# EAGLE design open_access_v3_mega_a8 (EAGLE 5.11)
DIGIKEY: 709-1189-1-ND

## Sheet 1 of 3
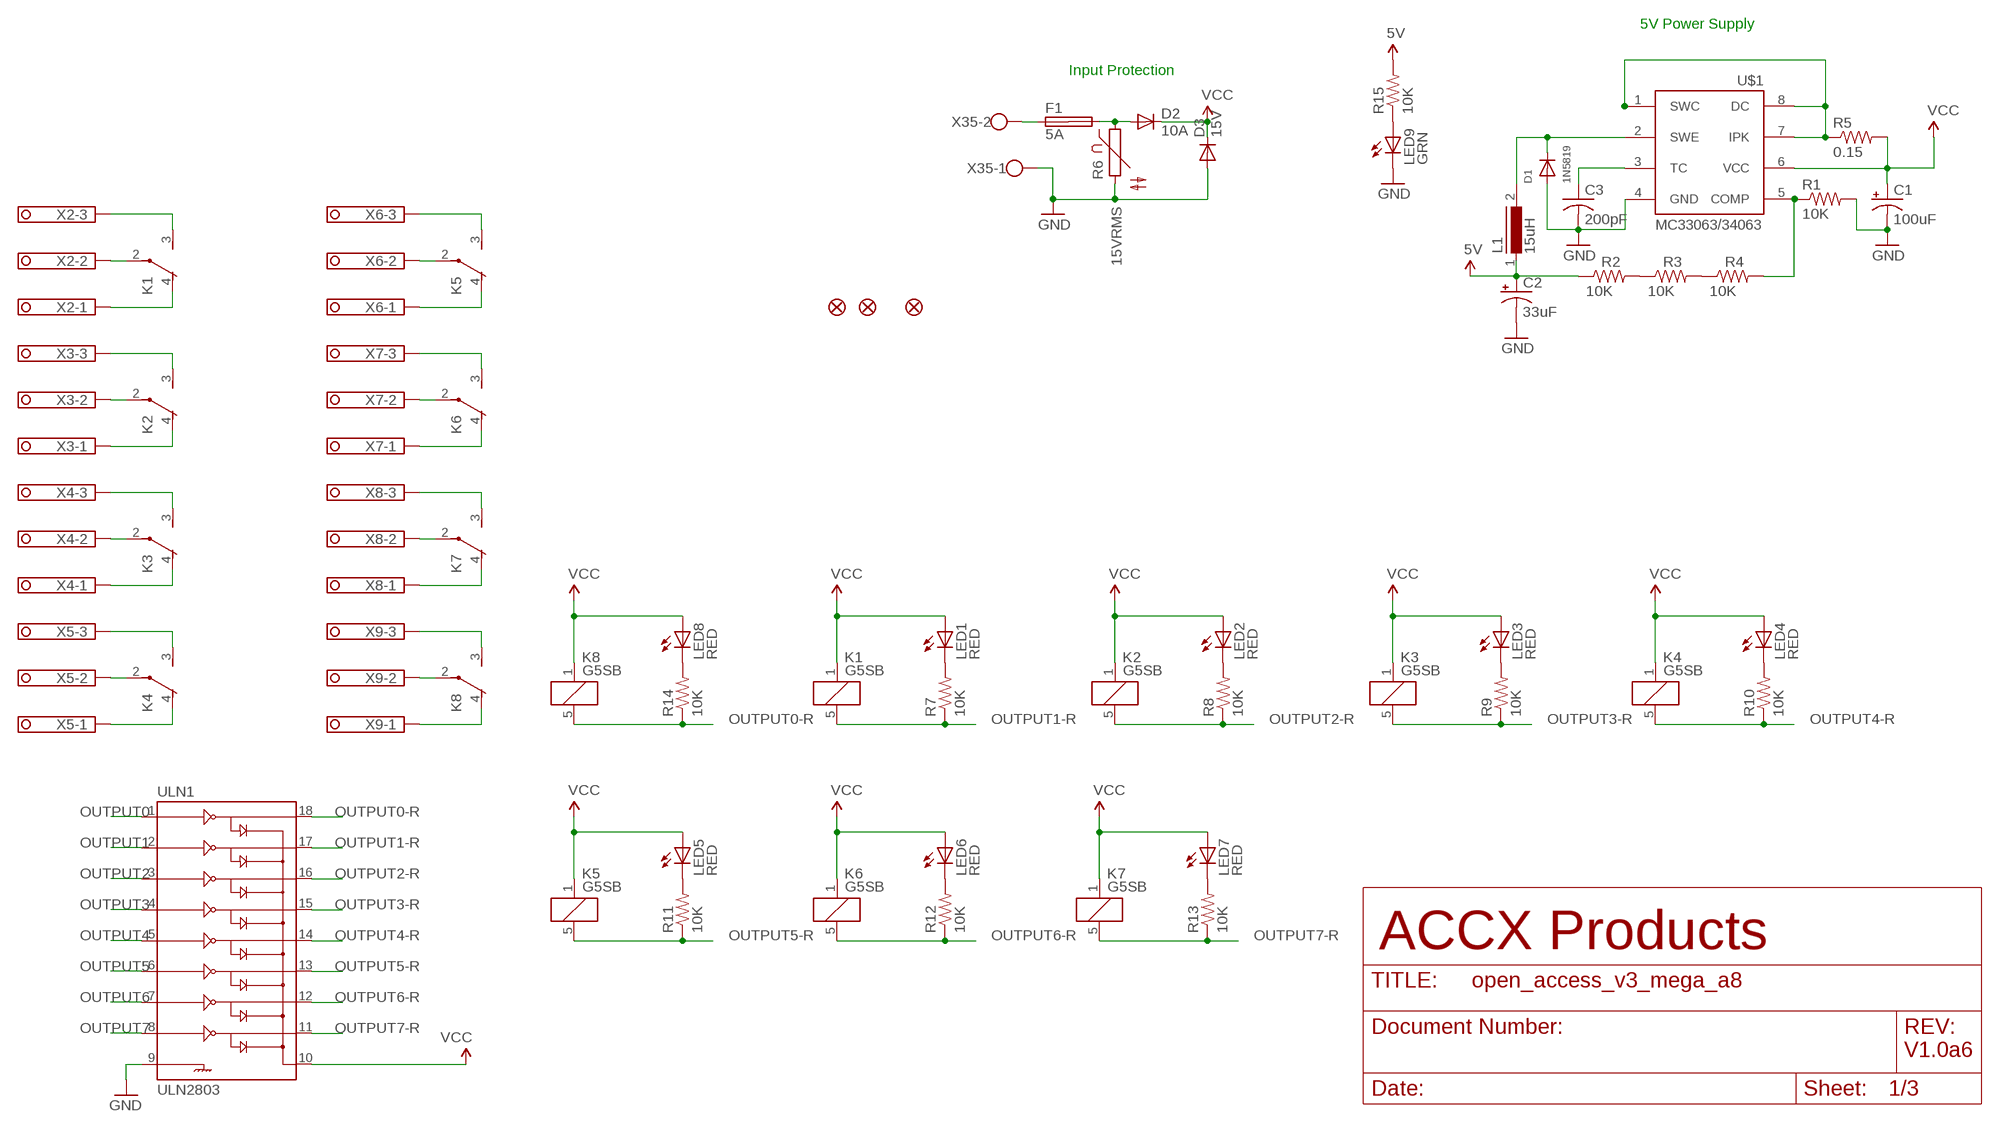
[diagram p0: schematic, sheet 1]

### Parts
C1  100uF  CPOL-US140CLH-0810  [140CLH-0810]
C2  33uF  CPOL-US153CLV-0605  [153CLV-0605]
C3  200pF  C-USC0805  [C0805]
D1  1N5819  DIODESOD-123  [SOD-123]
D2  10A  DIODE-SMC  [SMC]
D3  15V  DIODE-SOD123  [SOD123]
F1  5A  5X20MMCLIP  [SHK20Q]
JP3  FIDUCIAL1.5X3  [FIDUCIAL-1.5X3]
JP4  FIDUCIAL1.5X3  [FIDUCIAL-1.5X3]
JP5  FIDUCIAL1.5X3  [FIDUCIAL-1.5X3]
K1  G5SB  [G5SB]
K2  G5SB  [G5SB]
K3  G5SB  [G5SB]
K4  G5SB  [G5SB]
K5  G5SB  [G5SB]
K6  G5SB  [G5SB]
K7  G5SB  [G5SB]
K8  G5SB  [G5SB]
L1  15uH  SLF7045  [SLF7045]
LED1  RED  LEDCHIP-LED0805  [CHIP-LED0805]
LED2  RED  LEDCHIP-LED0805  [CHIP-LED0805]
LED3  RED  LEDCHIP-LED0805  [CHIP-LED0805]
LED4  RED  LEDCHIP-LED0805  [CHIP-LED0805]
LED5  RED  LEDCHIP-LED0805  [CHIP-LED0805]
LED6  RED  LEDCHIP-LED0805  [CHIP-LED0805]
LED7  RED  LEDCHIP-LED0805  [CHIP-LED0805]
LED8  RED  LEDCHIP-LED0805  [CHIP-LED0805]
LED9  GRN  LEDCHIP-LED0805  [CHIP-LED0805]
R1  10K  R-US_R0805  [R0805]
R2  10K  R-US_R0805  [R0805]
R3  10K  R-US_R0805  [R0805]
R4  10K  R-US_R0805  [R0805]
R5  0.15  R-US_R0805  [R0805]
R6  15VRMS  S10K40  [S10K40]
R7  10K  R-US_R0805  [R0805]
R8  10K  R-US_R0805  [R0805]
R9  10K  R-US_R0805  [R0805]
R10  10K  R-US_R0805  [R0805]
R11  10K  R-US_R0805  [R0805]
R12  10K  R-US_R0805  [R0805]
R13  10K  R-US_R0805  [R0805]
R14  10K  R-US_R0805  [R0805]
R15  10K  R-US_R0805  [R0805]
U$1  MC33063/MC34063D  [SO08]
ULN1  ULN2803  ULN2803SOICW  [SO18L]
X2  1751251  [1751251]
X3  1751251  [1751251]
X4  1751251  [1751251]
X5  1751251  [1751251]
X6  1751251  [1751251]
X7  1751251  [1751251]
X8  1751251  [1751251]
X9  1751251  [1751251]
X35  W237-102  [W237-102]

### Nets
5V [1A_power]: C2.+ L1.1 R2.1 R15.2 ; also sheet 2,3
GND: C1.- C2.- C3.2 D1.A D3.A LED9.C R1.2 R6.2 U$1.4(GND) ULN1.9 X35.1 ; also sheet 2,3
N$1 [1A_power]: R2.2 R3.1
N$2 [1A_power]: R3.2 R4.1
N$3 [1A_power]: R5.1 U$1.1(SWC) U$1.7(IPK) U$1.8(DC)
N$4: F1.1A X35.2
N$5: R1.1 R4.2 U$1.5(COMP)
N$6: C3.1 U$1.3(TC)
N$8 [1A_power]: D2.A F1.2A R6.1
N$9: LED2.C R8.2
N$10 [5A_power]: K1.2(U:P) X2.2
N$11 [5A_power]: K1.3(U:S) X2.3
N$12 [5A_power]: K1.4(U:O) X2.1
N$13 [5A_power]: K2.2(U:P) X3.2
N$14 [5A_power]: K2.3(U:S) X3.3
N$15 [5A_power]: K2.4(U:O) X3.1
N$16 [5A_power]: K3.2(U:P) X4.2
N$17 [5A_power]: K3.3(U:S) X4.3
N$18 [5A_power]: K3.4(U:O) X4.1
N$19 [5A_power]: K4.2(U:P) X5.2
N$20 [5A_power]: K4.3(U:S) X5.3
N$21 [5A_power]: K4.4(U:O) X5.1
N$22 [5A_power]: K5.2(U:P) X6.2
N$23 [5A_power]: K5.3(U:S) X6.3
N$24 [5A_power]: K5.4(U:O) X6.1
N$25 [5A_power]: K6.2(U:P) X7.2
N$26 [5A_power]: K6.3(U:S) X7.3
N$27 [5A_power]: K6.4(U:O) X7.1
N$28 [5A_power]: K7.2(U:P) X8.2
N$29 [5A_power]: K7.3(U:S) X8.3
N$30 [5A_power]: K7.4(U:O) X8.1
N$31 [5A_power]: K8.2(U:P) X9.2
N$32 [5A_power]: K8.3(U:S) X9.3
N$34: LED3.C R9.2
N$35: LED1.C R7.2
N$36: LED4.C R10.2
N$37: LED5.C R11.2
N$38: LED6.C R12.2
N$39: LED7.C R13.2
N$40: LED8.C R14.2
N$41: LED9.A R15.1
N$81: D1.C L1.2 U$1.2(SWE)
N$255 [5A_power]: K8.4(U:O) X9.1
OUTPUT0: ULN1.1 ; also sheet 3
OUTPUT0-R: K8.5 R14.1 ULN1.18
OUTPUT1: ULN1.2 ; also sheet 3
OUTPUT1-R: K1.5 R7.1 ULN1.17
OUTPUT2: ULN1.3 ; also sheet 3
OUTPUT2-R: K2.5 R8.1 ULN1.16
OUTPUT3: ULN1.4 ; also sheet 3
OUTPUT3-R: K3.5 R9.1 ULN1.15
OUTPUT4: ULN1.5 ; also sheet 3
OUTPUT4-R: K4.5 R10.1 ULN1.14
OUTPUT5: ULN1.6 ; also sheet 3
OUTPUT5-R: K5.5 R11.1 ULN1.13
OUTPUT6: ULN1.7 ; also sheet 3
OUTPUT6-R: K6.5 R12.1 ULN1.12
OUTPUT7: ULN1.8 ; also sheet 3
OUTPUT7-R: K7.5 R13.1 ULN1.11
VCC [1A_power]: C1.+ D2.C D3.C K1.1 K2.1 K3.1 K4.1 K5.1 K6.1 K7.1 K8.1 LED1.A LED2.A LED3.A LED4.A LED5.A LED6.A LED7.A LED8.A R5.2 U$1.6(VCC) ULN1.10 ; also sheet 2
Unconnected: F1.1B F1.2B

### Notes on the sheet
- 5V Power Supply
- Input Protection
- ACCX Products
- V1.0a6

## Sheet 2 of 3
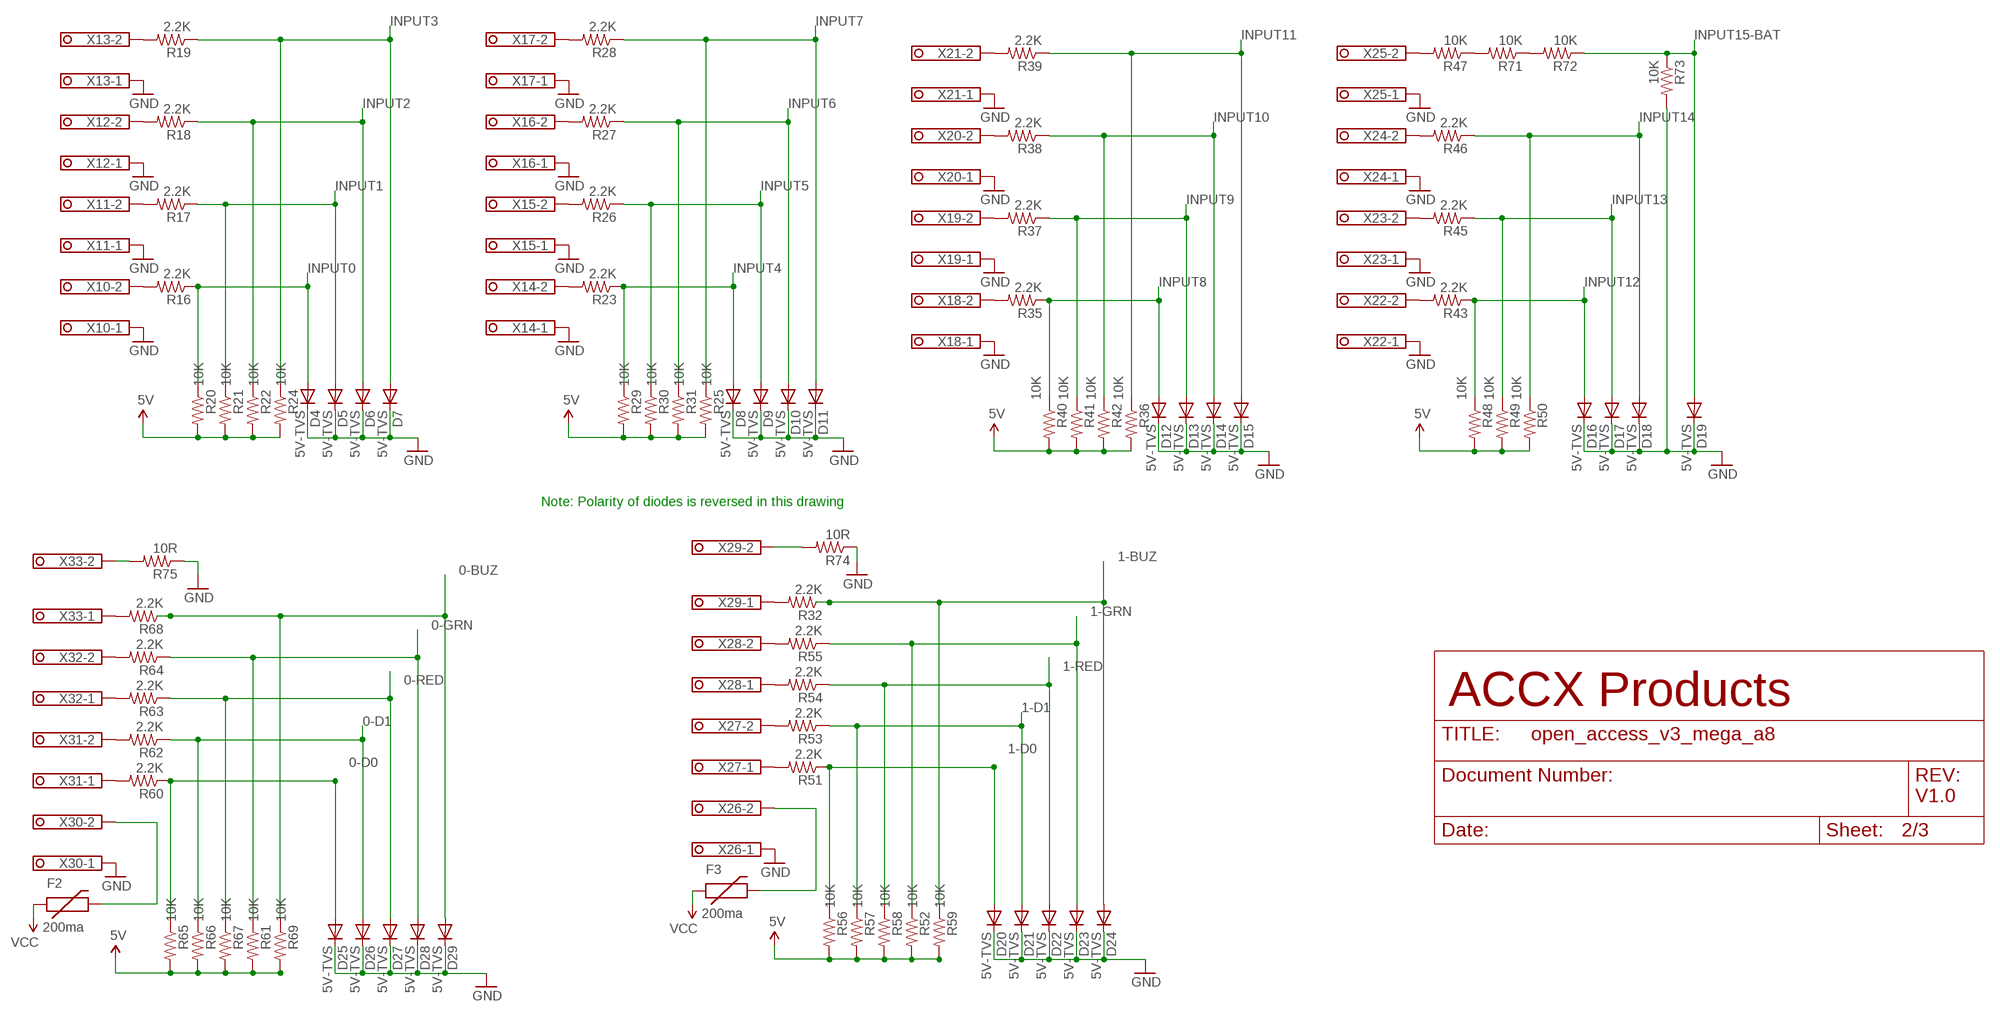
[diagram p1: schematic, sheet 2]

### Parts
D4  5V-TVS  DIODE-SOD123  [SOD123]
D5  5V-TVS  DIODE-SOD123  [SOD123]
D6  5V-TVS  DIODE-SOD123  [SOD123]
D7  5V-TVS  DIODE-SOD123  [SOD123]
D8  5V-TVS  DIODE-CREV  [SOT123-CREV]
D9  5V-TVS  DIODE-CREV  [SOT123-CREV]
D10  5V-TVS  DIODE-CREV  [SOT123-CREV]
D11  5V-TVS  DIODE-CREV  [SOT123-CREV]
D12  5V-TVS  DIODE-SOD123  [SOD123]
D13  5V-TVS  DIODE-SOD123  [SOD123]
D14  5V-TVS  DIODE-SOD123  [SOD123]
D15  5V-TVS  DIODE-SOD123  [SOD123]
D16  5V-TVS  DIODE-SOD123  [SOD123]
D17  5V-TVS  DIODE-SOD123  [SOD123]
D18  5V-TVS  DIODE-SOD123  [SOD123]
D19  5V-TVS  DIODE-SOD123  [SOD123]
D20  5V-TVS  DIODE-SOD123  [SOD123]
D21  5V-TVS  DIODE-SOD123  [SOD123]
D22  5V-TVS  DIODE-SOD123  [SOD123]
D23  5V-TVS  DIODE-SOD123  [SOD123]
D24  5V-TVS  DIODE-SOD123  [SOD123]
D25  5V-TVS  DIODE-SOD123  [SOD123]
D26  5V-TVS  DIODE-SOD123  [SOD123]
D27  5V-TVS  DIODE-SOD123  [SOD123]
D28  5V-TVS  DIODE-SOD123  [SOD123]
D29  5V-TVS  DIODE-SOD123  [SOD123]
F2  200ma  PTCSMD  [PTC-1206]
F3  200ma  PTCSMD  [PTC-1206]
R16  2.2K  R-US_R0805  [R0805]
R17  2.2K  R-US_R0805  [R0805]
R18  2.2K  R-US_R0805  [R0805]
R19  2.2K  R-US_R0805  [R0805]
R20  10K  R-US_R0805  [R0805]
R21  10K  R-US_R0805  [R0805]
R22  10K  R-US_R0805  [R0805]
R23  2.2K  R-US_R0805  [R0805]
R24  10K  R-US_R0805  [R0805]
R25  10K  R-US_R0805  [R0805]
R26  2.2K  R-US_R0805  [R0805]
R27  2.2K  R-US_R0805  [R0805]
R28  2.2K  R-US_R0805  [R0805]
R29  10K  R-US_R0805  [R0805]
R30  10K  R-US_R0805  [R0805]
R31  10K  R-US_R0805  [R0805]
R32  2.2K  R-US_R0805  [R0805]
R35  2.2K  R-US_R0805  [R0805]
R36  10K  R-US_R0805  [R0805]
R37  2.2K  R-US_R0805  [R0805]
R38  2.2K  R-US_R0805  [R0805]
R39  2.2K  R-US_R0805  [R0805]
R40  10K  R-US_R0805  [R0805]
R41  10K  R-US_R0805  [R0805]
R42  10K  R-US_R0805  [R0805]
R43  2.2K  R-US_R0805  [R0805]
R45  2.2K  R-US_R0805  [R0805]
R46  2.2K  R-US_R0805  [R0805]
R47  10K  R-US_R0805  [R0805]
R48  10K  R-US_R0805  [R0805]
R49  10K  R-US_R0805  [R0805]
R50  10K  R-US_R0805  [R0805]
R51  2.2K  R-US_R0805  [R0805]
R52  10K  R-US_R0805  [R0805]
R53  2.2K  R-US_R0805  [R0805]
R54  2.2K  R-US_R0805  [R0805]
R55  2.2K  R-US_R0805  [R0805]
R56  10K  R-US_R0805  [R0805]
R57  10K  R-US_R0805  [R0805]
R58  10K  R-US_R0805  [R0805]
R59  10K  R-US_R0805  [R0805]
R60  2.2K  R-US_R0805  [R0805]
R61  10K  R-US_R0805  [R0805]
R62  2.2K  R-US_R0805  [R0805]
R63  2.2K  R-US_R0805  [R0805]
R64  2.2K  R-US_R0805  [R0805]
R65  10K  R-US_R0805  [R0805]
R66  10K  R-US_R0805  [R0805]
R67  10K  R-US_R0805  [R0805]
R68  2.2K  R-US_R0805  [R0805]
R69  10K  R-US_R0805  [R0805]
R71  10K  R-US_R0805  [R0805]
R72  10K  R-US_R0805  [R0805]
R73  10K  R-US_R0805  [R0805]
R74  10R  R-US_R0805  [R0805]
R75  10R  R-US_R0805  [R0805]
X10  1751248  [1751248]
X11  1751248  [1751248]
X12  1751248  [1751248]
X13  1751248  [1751248]
X14  1751248  [1751248]
X15  1751248  [1751248]
X16  1751248  [1751248]
X17  1751248  [1751248]
X18  1751248  [1751248]
X19  1751248  [1751248]
X20  1751248  [1751248]
X21  1751248  [1751248]
X22  1751248  [1751248]
X23  1751248  [1751248]
X24  1751248  [1751248]
X25  1751248  [1751248]
X26  1751248  [1751248]
X27  1751248  [1751248]
X28  1751248  [1751248]
X29  1751248  [1751248]
X30  1751248  [1751248]
X31  1751248  [1751248]
X32  1751248  [1751248]
X33  1751248  [1751248]

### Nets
0-BUZ: D29.A R68.1 R69.1 ; also sheet 3
0-D0: D25.A R60.1 R65.1 ; also sheet 3
0-D1: D26.A R62.1 R66.1 ; also sheet 3
0-GRN: D28.A R61.1 R64.1 ; also sheet 3
0-RED: D27.A R63.1 R67.1 ; also sheet 3
1-BUZ: D24.A R32.1 R59.1 ; also sheet 3
1-D0: D20.A R51.1 R56.1 ; also sheet 3
1-D1: D21.A R53.1 R57.1 ; also sheet 3
1-GRN: D23.A R52.1 R55.1 ; also sheet 3
1-RED: D22.A R54.1 R58.1 ; also sheet 3
5V [1A_power]: R20.2 R21.2 R22.2 R24.2 R25.2 R29.2 R30.2 R31.2 R36.2 R40.2 R41.2 R42.2 R48.2 R49.2 R50.2 R52.2 R56.2 R57.2 R58.2 R59.2 R61.2 R65.2 R66.2 R67.2 R69.2 ; also sheet 1,3
GND: D4.C D5.C D6.C D7.C D8.C D9.C D10.C D11.C D12.C D13.C D14.C D15.C D16.C D17.C D18.C D19.C D20.C D21.C D22.C D23.C D24.C D25.C D26.C D27.C D28.C D29.C R73.2 R74.1 R75.1 X10.1 X11.1 X12.1 X13.1 X14.1 X15.1 X16.1 X17.1 X18.1 X19.1 X20.1 X21.1 X22.1 X23.1 X24.1 X25.1 X26.1 X30.1 ; also sheet 1,3
INPUT0: D4.A R16.1 R20.1 ; also sheet 3
INPUT1: D5.A R17.1 R21.1 ; also sheet 3
INPUT2: D6.A R18.1 R22.1 ; also sheet 3
INPUT3: D7.A R19.1 R24.1 ; also sheet 3
INPUT4: D8.A R23.1 R29.1 ; also sheet 3
INPUT5: D9.A R26.1 R30.1 ; also sheet 3
INPUT6: D10.A R27.1 R31.1 ; also sheet 3
INPUT7: D11.A R25.1 R28.1 ; also sheet 3
INPUT8: D12.A R35.1 R40.1 ; also sheet 3
INPUT9: D13.A R37.1 R41.1 ; also sheet 3
INPUT10: D14.A R38.1 R42.1 ; also sheet 3
INPUT11: D15.A R36.1 R39.1 ; also sheet 3
INPUT12: D16.A R43.1 R48.1 ; also sheet 3
INPUT13: D17.A R45.1 R49.1 ; also sheet 3
INPUT14: D18.A R46.1 R50.1 ; also sheet 3
INPUT15-BAT: D19.A R72.1 R73.1 ; also sheet 3
N$46 [1A_power]: F2.2 X30.2
N$47: F3.2 X26.2
N$50: R16.2 X10.2
N$51: R17.2 X11.2
N$52: R18.2 X12.2
N$53: R19.2 X13.2
N$54: R23.2 X14.2
N$55: R26.2 X15.2
N$56: R27.2 X16.2
N$57: R28.2 X17.2
N$61: R35.2 X18.2
N$62: R37.2 X19.2
N$63: R38.2 X20.2
N$64: R39.2 X21.2
N$65: R43.2 X22.2
N$66: R45.2 X23.2
N$67: R46.2 X24.2
N$68: R47.2 X25.2
N$69: R51.2 X27.1
N$70: R53.2 X27.2
N$71: R54.2 X28.1
N$72: R55.2 X28.2
N$73: R32.2 X29.1
N$74: R62.2 X31.2
N$75: R60.2 X31.1
N$76: R63.2 X32.1
N$77: R64.2 X32.2
N$78: R68.2 X33.1
N$82: R47.1 R71.2
N$83: R71.1 R72.2
N$84: R74.2 X29.2
N$85: R75.2 X33.2
VCC [1A_power]: F2.1 F3.1 ; also sheet 1

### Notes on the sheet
- Note: Polarity of diodes is reversed in this drawing
- ACCX Products
- V1.0

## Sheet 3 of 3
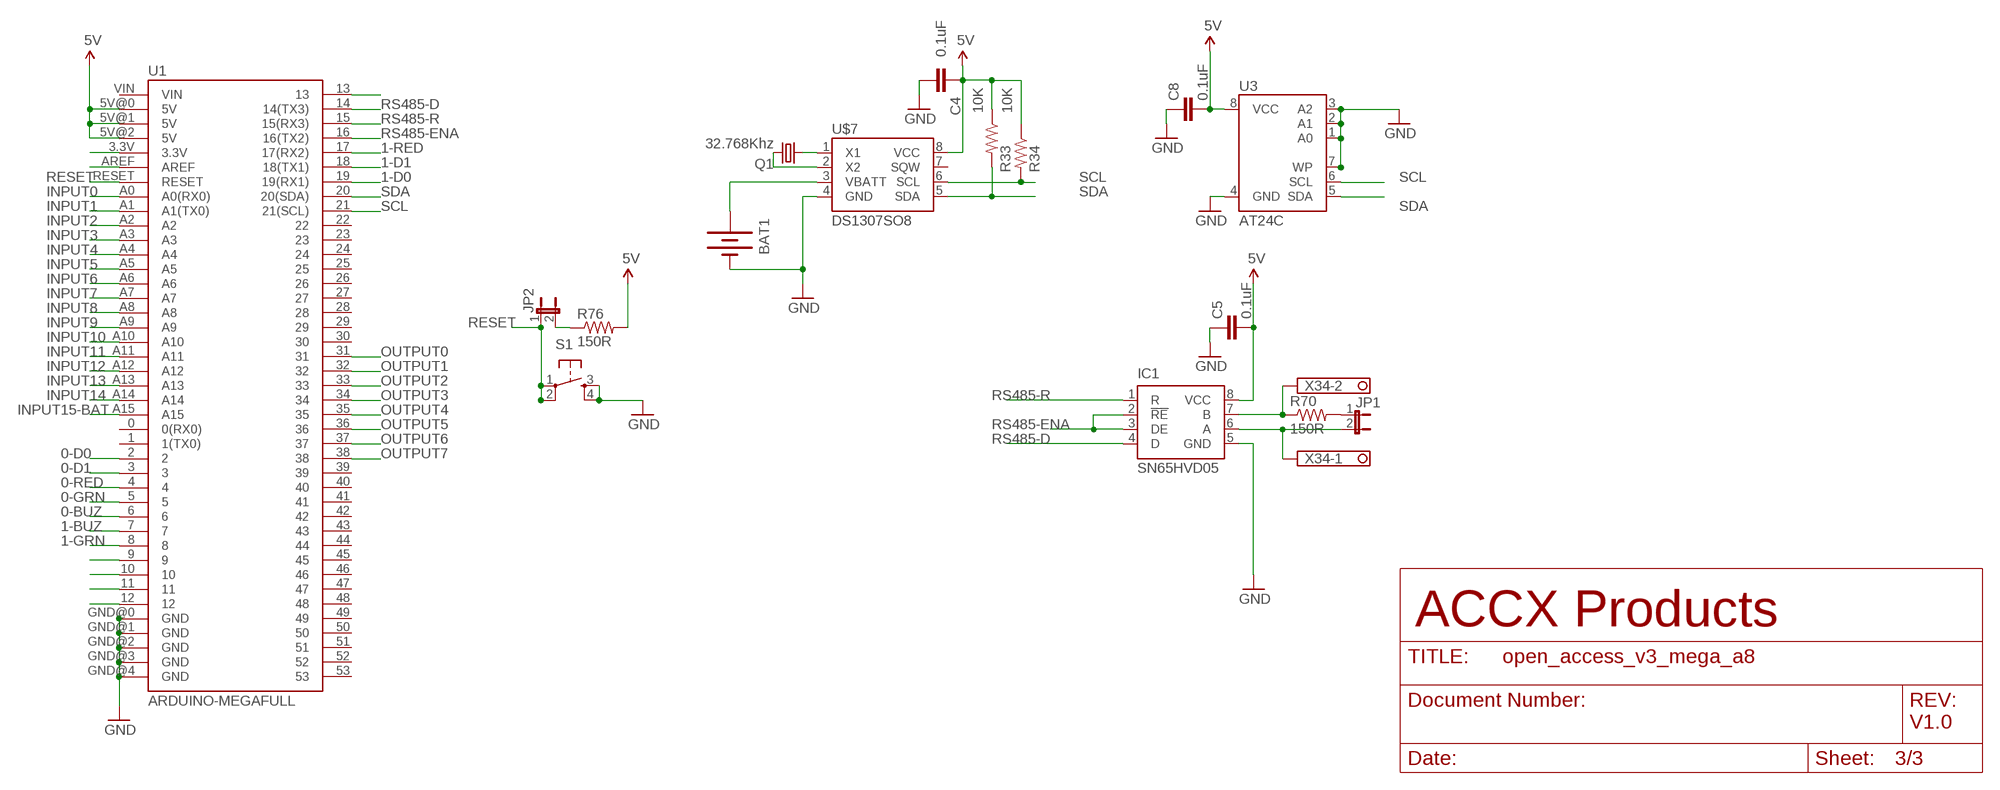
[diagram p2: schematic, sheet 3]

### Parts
BAT1  BATTERY20PTH  [BATTCOM_20MM_PTH]
C4  0.1uF  CAP0805  [0805]
C5  0.1uF  CAP0805  [0805]
C8  0.1uF  CAP0805  [0805]
IC1  SN65HVD05  SN65176D  [SO-08]
JP1  JP1E  [JP1]
JP2  JP1E  [JP1]
Q1  32.768Khz  CRYSTALMM20SS  [MM20SS]
R33  10K  R-US_R0805  [R0805]
R34  10K  R-US_R0805  [R0805]
R70  150R  R-US_R0805  [R0805]
R76  150R  R-US_R0805  [R0805]
S1  TAC_SWITCHSMD  [TACTILE_SWITCH_SMD]
U1  ARDUINO-MEGAFULL  [ARDUINO_MEGA]
U3  AT24C  [SOIC8]
U$7  DS1307SO8  [SO08]
X34  1751248  [1751248]

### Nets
0-BUZ: U1.6 ; also sheet 2
0-D0: U1.2 ; also sheet 2
0-D1: U1.3 ; also sheet 2
0-GRN: U1.5 ; also sheet 2
0-RED: U1.4 ; also sheet 2
1-BUZ: U1.7 ; also sheet 2
1-D0: U1.19(19(RX1)) ; also sheet 2
1-D1: U1.18(18(TX1)) ; also sheet 2
1-GRN: U1.8 ; also sheet 2
1-RED: U1.17(17(RX2)) ; also sheet 2
5V [1A_power]: C4.2 C5.2 C8.2 IC1.8(VCC) R33.1 R34.1 R76.2 U1.5V@0(5V) U1.5V@1(5V) U1.5V@2(5V) U3.8(VCC) U$7.8(VCC) ; also sheet 1,2
GND: BAT1.2(-) C4.1 C5.1 C8.1 IC1.5(GND) S1.3 S1.4 U1.GND@0(GND) U1.GND@1(GND) U1.GND@2(GND) U1.GND@3(GND) U1.GND@4(GND) U3.1(A0) U3.2(A1) U3.3(A2) U3.4(GND) U3.7(WP) U$7.4(GND) ; also sheet 1,2
INPUT0: U1.A0(A0(RX0)) ; also sheet 2
INPUT1: U1.A1(A1(TX0)) ; also sheet 2
INPUT2: U1.A2 ; also sheet 2
INPUT3: U1.A3 ; also sheet 2
INPUT4: U1.A4 ; also sheet 2
INPUT5: U1.A5 ; also sheet 2
INPUT6: U1.A6 ; also sheet 2
INPUT7: U1.A7 ; also sheet 2
INPUT8: U1.A8 ; also sheet 2
INPUT9: U1.A9 ; also sheet 2
INPUT10: U1.A10 ; also sheet 2
INPUT11: U1.A11 ; also sheet 2
INPUT12: U1.A12 ; also sheet 2
INPUT13: U1.A13 ; also sheet 2
INPUT14: U1.A14 ; also sheet 2
INPUT15-BAT: U1.A15 ; also sheet 2
N$42: U1.12
N$43: U1.11
N$44: U1.10
N$45: U1.9
N$49: IC1.6(A) JP1.2 X34.1
N$58: Q1.1 U$7.1(X1)
N$59: Q1.4 U$7.2(X2)
N$60: BAT1.1(+) U$7.3(VBATT)
N$79: JP2.2 R76.1
N$86: JP1.1 R70.2
N$91: U1.3.3V
N$92: U1.AREF
N$93: U1.13
OUTPUT0: U1.31 ; also sheet 1
OUTPUT1: U1.32 ; also sheet 1
OUTPUT2: U1.33 ; also sheet 1
OUTPUT3: U1.34 ; also sheet 1
OUTPUT4: U1.35 ; also sheet 1
OUTPUT5: U1.36 ; also sheet 1
OUTPUT6: U1.37 ; also sheet 1
OUTPUT7: U1.38 ; also sheet 1
RESET: JP2.1 S1.1 S1.2 U1.RESET
RS485-B: IC1.7(B) R70.1 X34.2
RS485-D: IC1.4(D) U1.14(14(TX3))
RS485-ENA: IC1.2(!RE) IC1.3(DE) U1.16(16(TX2))
RS485-R: IC1.1(R) U1.15(15(RX3))
SCL: R34.2 U1.21(21(SCL)) U3.6(SCL) U$7.6(SCL)
SDA: R33.2 U1.20(20(SDA)) U3.5(SDA) U$7.5(SDA)
Unconnected: U1.0(0(RX0)) U1.1(1(TX0)) U1.22 U1.23 U1.24 U1.25 U1.26 U1.27 U1.28 U1.29 U1.30 U1.39 U1.40 U1.41 U1.42 U1.43 U1.44 U1.45 U1.46 U1.47 U1.48 U1.49 U1.50 U1.51 U1.52 U1.53 U1.VIN U$7.7(SQW)

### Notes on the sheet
- ACCX Products
- V1.0

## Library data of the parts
BAT1 = SparkFun:BATTERY: Battery Holders
C1 C2 = resistor:CPOL-US: POLARIZED CAPACITOR, American symbol
C3 = resistor:C-US: CAPACITOR, American symbol
C4 C5 C8 = SparkFun:CAP: Capacitor
D1 = adafruit:DIODE: Diode
D2-D7 D12-D29 = diode:DIODE-: DIODE
D8-D11 = 23B_Shop_Library:DIODE-CREV
F1 = 23B_Shop_Library:5X20MMCLIP: FUSE HOLDER Littelfuse 01110506H 5x20mm clips. Mouser part #576-01110506H
F2 F3 = SparkFun:PTC: Resettable Fuse PTC
IC1 = texas:SN65176: DIFFERENTIAL BUS TRANSCEIVER Source: http://focus.ti.com .. sn65176b.pdf; MF: TEXAS INSTRUMENTS; MPN: SN65176BD; OC_FARNELL: 9589970; OC_NEWARK: 08F5891
JP1 JP2 = jumper:JP1E: JUMPER
JP3-JP5 = SparkFun:FIDUCIAL: Fiducial Alignment Points
K1-K8 = relay:G5SB: Compact Single-pole Relay for Switching 5 A Source: http://www.omron.com/ecb/products/pry/121/g5sb.html; OC_FARNELL: unknown; OC_NEWARK: unknown
L1 = inductors:SLF7045: SMD Inductors(Coils) For Power Line (Wound, Magnetic Shielded)
LED1-LED9 = adafruit:LED: LED
Q1 = crystal:CRYSTAL: CRYSTAL; OC_FARNELL: unknown; OC_NEWARK: unknown
R1-R5 R7-R43 R45-R76 = resistor:R-US_: RESISTOR, American symbol
R6 = varistor:S10K40: VARISTOR
S1 = SparkFun:TAC_SWITCH: Momentary Switch Button commonly used for reset or general input. Spark Fun Electronics SKU : COM-00097
U1 = SparkFun:ARDUINO-MEGA: Arduino Mega footprint connections
U3 = atmel:AT24C*: 2-wire serial EEPROM
U$1 = adafruit:MC33063/MC34063: MC33063 and MC34063 Basic DC/DC converter with internal power-NPN transistor, 100KHz, 1.5A peak switch current. 3-40 input/output.
U$7 = SparkFun:DS1307
ULN1 = SparkFun:ULN2803: Darlington Driver ULN2803 Darlington array. 500mA max per channel, 8-channel package. Spark Fun Electronics SKU : COM-00312
X2-X9 = con-phoenix-350:1751251: MKDS 1/ 3-3,5 Printklemme Nennstrom: 10 A Bemessungsspannung: 160 V Raster: 3,5 mm Polzahl: 3 Montageart: Löten Anschlussart: Schraubanschluss Anschlussrichtung vom Leiter zur Platine: 0° Source: http://eshop.phoenixcontact.com .. 1751251.pdf; OC_FARNELL: unknown; OC_NEWARK: unknown
X10-X34 = con-phoenix-350:1751248: MKDS 1/ 2-3,5 Printklemme; OC_FARNELL: unknown; OC_NEWARK: unknown
X35 = 23B_Shop_Library:W237-102: WAGO SCREW CLAMP

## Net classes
0 signals: width 0.254 mm, clearance 0.254 mm
1 power signals: width 0.305 mm, clearance 0.305 mm
2 1A_power: width 0.406 mm, clearance 0.305 mm
3 5A_power: width 2.54 mm, clearance 0.61 mm

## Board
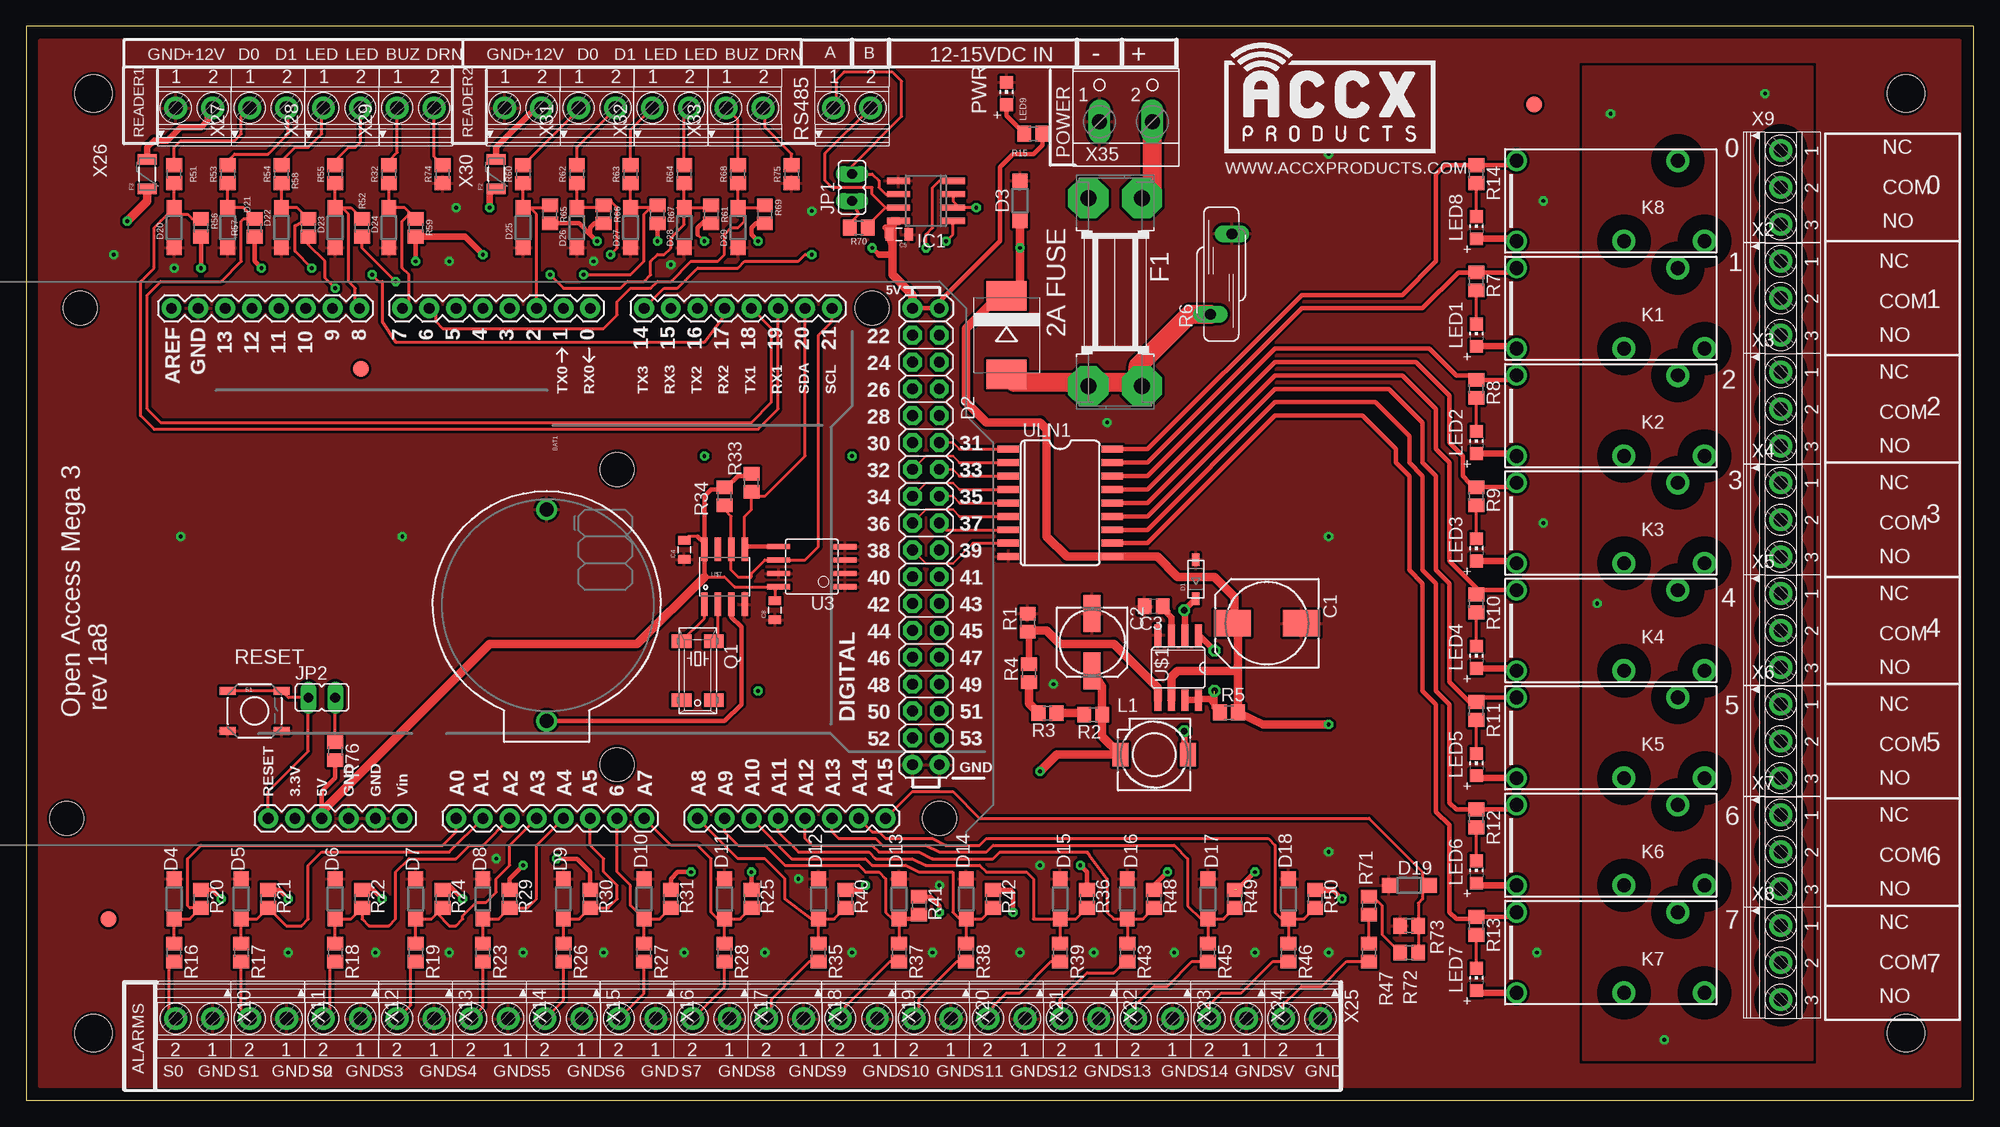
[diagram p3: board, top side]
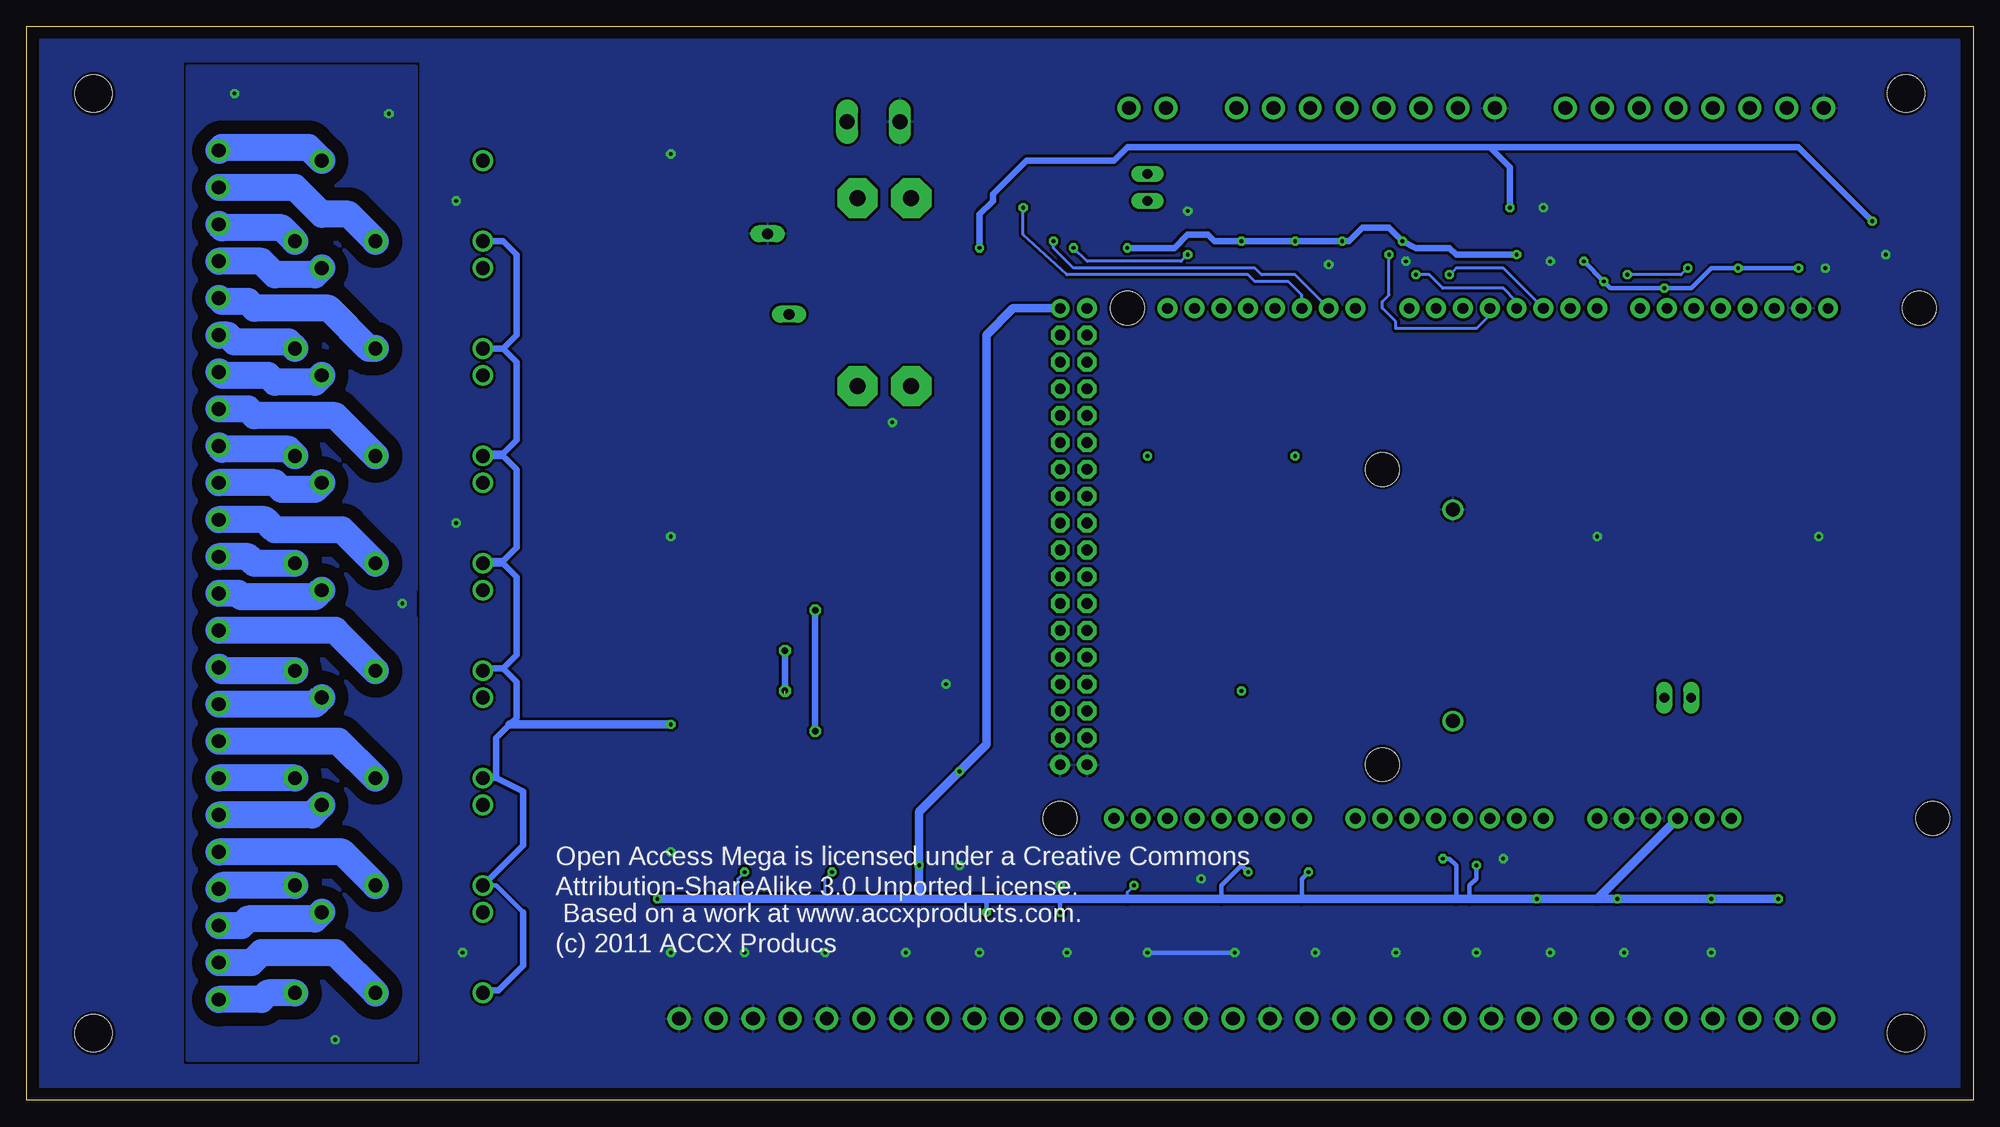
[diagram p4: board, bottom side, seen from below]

Size 184.15 x 101.6 mm. Coordinates in mm from the lower left corner, seen from the top.
Outline: 0,0 184.15,0 184.15,101.6 0,101.6 0,0
Copper layers (1*16): Top 0.035mm / dielectric 1.5mm / Bottom 0.035mm
Design rules "SparkFun": minimum track width 8mil, minimum drill 20mil, track to track 8mil, track to pad 8mil, pad to pad 8mil, via to via 8mil, smd to smd 8mil, copper to edge 10mil, drill to drill 8mil, minimum pad ring 12mil, minimum via ring 10mil, stop-mask expansion 4mil, vias tented up to drill 25mil, thermal gap 10mil
Holes 3.56 mm at 6.35,6.35 6.35,95.25 177.8,6.35 177.8,95.25

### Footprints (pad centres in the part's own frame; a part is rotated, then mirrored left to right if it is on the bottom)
BATTCOM_20MM_PTH = drill 1.3 round: 1 20,0; 2 0,0
140CLH-0810 = smd 3.5 x 2.5: + 3.25,0; - -3.25,0
153CLV-0605 = smd 3.5 x 1.6: + 2.7,0; - -2.7,0
C0805 = smd 1.3 x 1.5: 1 -0.85,0; 2 0.85,0
0805 = smd 0.8 x 1.2: 1 -0.9,0; 2 0.9,0
SOD-123 = smd 1.2 x 0.7: A 1.85,0; C -1.85,0
SMC = smd 2.8 x 3.8: A 3.7,0; C -3.7,0
SOD123 = smd 1.4 x 1.4: A 1.9,0; C -1.9,0
SOT123-CREV = smd 1.4 x 1.4: A 1.9,0; C -1.9,0
SHK20Q = drill 1.5 pad 3.81 octagon: 1A -8.89,2.54; 1B -8.89,-2.54; 2A 8.89,2.54; 2B 8.89,-2.54
PTC-1206 = smd 1 x 1.8: 1 -1.4,0; 2 1.4,0
SO-08 = smd 0.6 x 2.2: 1 -1.905,-2.6; 2 -0.635,-2.6; 3 0.635,-2.6; 4 1.905,-2.6; 5 1.905,2.6; 6 0.635,2.6; 7 -0.635,2.6; 8 -1.905,2.6
JP1 = drill 0.914 long: 1 0,-1.27; 2 0,1.27
FIDUCIAL-1.5X3 = smd 1.5 x 1.5: 1 0,0
G5SB = drill 1.3 pad 1.93 round: 1 7.62,3.81; 5 7.62,-3.81 | drill 1.3 pad 2.184 round: 2 -2.54,3.81; 3 -10.16,3.81; 4 -7.62,-3.81
SLF7045 = smd 1.5 x 2.2: 1 -3.2,0; 2 3.2,0
CHIP-LED0805 = smd 1.2 x 1.2: A 0,-1.05; C 0,1.05
MM20SS = smd 1.27 x 1.88: 1 -2.794,-1.524; 2 2.794,-1.524; 3 2.794,1.524; 4 -2.794,1.524
R0805 = smd 1.3 x 1.5: 1 -0.85,0; 2 0.85,0
S10K40 = drill 1.016 long: 1 -1.016,-3.81; 2 1.016,3.81
TACTILE_SWITCH_SMD = smd 1.524 x 0.762: 1 -2.54,1.905; 2 2.54,1.905; 3 -2.54,-1.905; 4 2.54,-1.905
ARDUINO_MEGA = drill 1.016 pad 1.88 round: 0 63.5,50.8; 1 60.96,50.8; 2 58.42,50.8; 3 55.88,50.8; 3.3V 35.56,2.54; 4 53.34,50.8; 5 50.8,50.8; 5V@0 38.1,2.54; 5V@1 93.98,50.8; 6 48.26,50.8; 7 45.72,50.8; 8 41.656,50.8; 9 39.116,50.8; 10 36.576,50.8; 11 34.036,50.8; 12 31.496,50.8; 13 28.956,50.8; 14 68.58,50.8; 15 71.12,50.8; 16 73.66,50.8; 17 76.2,50.8; 18 78.74,50.8; 19 81.28,50.8; 20 83.82,50.8; 21 86.36,50.8; A0 50.8,2.54; A1 53.34,2.54; A2 55.88,2.54; A3 58.42,2.54; A4 60.96,2.54; A5 63.5,2.54; A6 66.04,2.54; A7 68.58,2.54; A8 73.66,2.54; A9 76.2,2.54; A10 78.74,2.54; A11 81.28,2.54; A12 83.82,2.54; A13 86.36,2.54; A14 88.9,2.54; A15 91.44,2.54; AREF 23.876,50.8; GND@0 40.64,2.54; GND@1 43.18,2.54; GND@2 93.98,7.62; GND@3 96.52,7.62; GND@4 26.416,50.8; RESET 33.02,2.54; VIN 45.72,2.54 | drill 1.016 pad 1.778 round: 5V@2 96.52,50.8 | drill 1.016 pad 1.778 octagon: 22 93.98,48.26; 23 96.52,48.26; 24 93.98,45.72; 25 96.52,45.72; 26 93.98,43.18; 27 96.52,43.18; 28 93.98,40.64; 29 96.52,40.64; 30 93.98,38.1; 31 96.52,38.1; 32 93.98,35.56; 33 96.52,35.56; 34 93.98,33.02; 35 96.52,33.02; 36 93.98,30.48; 37 96.52,30.48; 38 93.98,27.94; 39 96.52,27.94; 40 93.98,25.4; 41 96.52,25.4; 42 93.98,22.86; 43 96.52,22.86; 44 93.98,20.32; 45 96.52,20.32; 46 93.98,17.78; 47 96.52,17.78; 48 93.98,15.24; 49 96.52,15.24; 50 93.98,12.7; 51 96.52,12.7; 52 93.98,10.16; 53 96.52,10.16 | hole 3.2: 15.24,50.8; 13.97,2.54; 66.04,35.56; 66.04,7.62; 90.17,50.8; 96.52,2.54
SOIC8 = smd 0.5 x 2.2: 1 -1.905,-3.154; 2 -0.645,-3.154; 3 0.625,-3.154; 4 1.895,-3.154; 5 1.905,3.154; 6 0.635,3.154; 7 -0.635,3.154; 8 -1.905,3.154
SO08 = smd 0.66 x 2.032: 1 -1.905,-3.073; 2 -0.635,-3.073; 3 0.635,-3.073; 4 1.905,-3.073; 5 1.905,3.073; 6 0.635,3.073; 7 -0.635,3.073; 8 -1.905,3.073
SO08' = smd 0.61 x 2.21: 1 -1.905,-2.616; 2 -0.635,-2.616; 3 0.635,-2.616; 4 1.905,-2.616; 5 1.905,2.616; 6 0.635,2.616; 7 -0.635,2.616; 8 -1.905,2.616
SO18L = smd 0.66 x 2.032: 1 -0.635,-4.902; 2 0.635,-4.902; 3 1.905,-4.902; 4 3.175,-4.902; 5 4.445,-4.902; 6 5.715,-4.902; 7 6.985,-4.902; 8 8.255,-4.902; 9 9.525,-4.902; 10 9.525,4.902; 11 8.255,4.902; 12 6.985,4.902; 13 5.715,4.902; 14 4.445,4.902; 15 3.175,4.902; 16 1.905,4.902; 17 0.635,4.902; 18 -0.635,4.902
1751251 = drill 1.3 pad 2.159 round: 1 -3.5,-0.1; 2 0,-0.1; 3 3.5,-0.1
1751248 = drill 1.3 pad 2.159 round: 1 -1.75,-0.1; 2 1.75,-0.1
W237-102 = drill 1.4 long: 1 -2.5,-1.27; 2 2.5,-1.27

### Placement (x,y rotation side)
BAT1  49.21,55.88 270 top
C1  117.35,45.12 180 top
C2  100.81,43.33 270 top
C3  106.63,46.74 180 top
C4  62.23,52.07 90 top
C5  82.55,81.92 180 top
C8  70.8,46.35 90 top
D1  110.63,49.3 90 top
D2  92.71,72.39 270 top
D3  93.98,85.09 90 top
D4  13.97,19.05 270 top
D5  20.32,19.05 270 top
D6  29.21,19.05 270 top
D7  36.83,19.05 270 top
D8  43.18,19.05 270 top
D9  50.8,19.05 270 top
D10  58.42,19.05 270 top
D11  66.04,19.05 270 top
D12  74.93,19.05 270 top
D13  82.55,19.05 270 top
D14  88.9,19.05 270 top
D15  97.79,19.05 270 top
D16  104.14,19.05 270 top
D17  111.76,19.05 270 top
D18  119.38,19.05 270 top
D19  130.81,20.32 0 top
D20  13.97,82.55 90 top
D21  19.05,82.55 90 top
D22  24.13,82.55 90 top
D23  29.21,82.55 90 top
D24  34.29,82.55 90 top
D25  46.99,82.55 90 top
D26  52.07,82.55 90 top
D27  57.15,82.55 90 top
D28  62.23,82.55 90 top
D29  67.31,82.55 90 top
F1  103,76.45 270 top
F2  44.45,87.63 90 top
F3  11.43,87.63 90 top
IC1  85.09,85.09 90 top
JP1  78.11,86.36 0 top
JP2  27.94,38.1 270 top
JP3  7.75,17.14 0 top
JP4  142.62,94.23 0 top
JP5  31.62,69.22 0 top
K1  148.59,74.93 180 top
K2  148.59,64.77 180 top
K3  148.59,54.61 180 top
K4  148.59,44.45 180 top
K5  148.59,34.29 180 top
K6  148.59,24.13 180 top
K7  148.59,13.97 180 top
K8  148.59,85.09 180 top
L1  106.68,32.7 0 top
LED1  137.16,72.39 0 top
LED2  137.16,62.23 0 top
LED3  137.16,52.07 0 top
LED4  137.16,41.91 0 top
LED5  137.16,31.75 0 top
LED6  137.16,21.59 0 top
LED7  137.16,11.43 0 top
LED8  137.16,82.55 0 top
LED9  92.71,95.25 0 top
Q1  63.5,40.64 270 top
R1  94.72,45.19 90 top
R2  100.91,36.47 180 top
R3  96.6,36.63 180 top
R4  94.84,40.41 90 top
R5  113.75,36.68 0 top
R6  113.03,78.17 0 top
R7  137.16,77.47 270 top
R8  137.16,67.31 270 top
R9  137.16,57.15 270 top
R10  137.16,46.99 270 top
R11  137.16,36.83 270 top
R12  137.16,26.67 270 top
R13  137.16,16.51 270 top
R14  137.16,87.63 270 top
R15  95.25,91.44 0 top
R16  13.97,13.97 270 top
R17  20.32,13.97 270 top
R18  29.21,13.97 270 top
R19  36.83,13.97 270 top
R20  16.51,19.05 90 top
R21  22.86,19.05 90 top
R22  31.75,19.05 90 top
R23  43.18,13.97 270 top
R24  39.37,19.05 90 top
R25  68.58,19.05 90 top
R26  50.8,13.97 270 top
R27  58.42,13.97 270 top
R28  66.04,13.97 270 top
R29  45.72,19.05 90 top
R30  53.34,19.05 90 top
R31  60.96,19.05 90 top
R32  34.29,87.63 90 top
R33  68.58,58.42 270 top
R34  66.04,57.15 270 top
R35  74.93,13.97 270 top
R36  100.33,19.05 90 top
R37  82.55,13.97 270 top
R38  88.9,13.97 270 top
R39  97.79,13.97 270 top
R40  77.47,19.05 90 top
R41  84.45,18.41 90 top
R42  91.44,19.05 90 top
R43  104.14,13.97 270 top
R45  111.76,13.97 270 top
R46  119.38,13.97 270 top
R47  127,13.97 270 top
R48  106.68,19.05 90 top
R49  114.3,19.05 90 top
R50  121.92,19.05 90 top
R51  13.97,87.63 90 top
R52  31.75,82.55 270 top
R53  19.05,87.63 90 top
R54  24.13,87.63 90 top
R55  29.21,87.63 90 top
R56  16.51,82.55 270 top
R57  21.59,82.55 270 top
R58  26.67,82.55 270 top
R59  36.83,82.55 270 top
R60  46.99,87.63 90 top
R61  64.77,83.82 270 top
R62  52.07,87.63 90 top
R63  57.15,87.63 90 top
R64  62.23,87.63 90 top
R65  49.53,83.82 270 top
R66  54.61,83.82 270 top
R67  59.69,83.82 270 top
R68  67.31,87.63 90 top
R69  69.85,83.82 270 top
R70  78.74,82.55 180 top
R71  127,18.41 270 top
R72  130.81,13.97 180 top
R73  130.81,16.51 180 top
R74  39.37,87.63 90 top
R75  72.39,87.63 90 top
R76  29.21,33.02 270 top
S1  21.59,36.83 0 top
U1  -10.16,24.13 0 top
U3  74.3,50.48 90 top
U$1  108.97,40.94 180 top
U$2  [ACCX_LOGO_TOP]  123.19,92.71 0 top
U$7  DS1307SO8  [SO08']  66.04,49.53 0 top
ULN1  97.79,60.96 270 top
X2  166.05,75.88 270 top
X3  166.05,65.41 270 top
X4  166.05,54.93 270 top
X5  166.05,44.45 270 top
X6  166.05,33.97 270 top
X7  166.05,23.5 270 top
X8  166.05,13.02 270 top
X9  166.05,86.36 270 top
X10  15.88,7.62 180 top
X11  22.86,7.62 180 top
X12  29.84,7.62 180 top
X13  36.83,7.62 180 top
X14  43.81,7.62 180 top
X15  50.8,7.62 180 top
X16  57.78,7.62 180 top
X17  64.77,7.62 180 top
X18  71.75,7.62 180 top
X19  78.74,7.62 180 top
X20  85.72,7.62 180 top
X21  92.71,7.62 180 top
X22  99.69,7.62 180 top
X23  106.68,7.62 180 top
X24  113.67,7.62 180 top
X25  120.65,7.62 180 top
X26  15.88,93.98 0 top
X27  22.86,93.98 0 top
X28  29.84,93.98 0 top
X29  36.83,93.98 0 top
X30  46.99,93.98 0 top
X31  53.98,93.98 0 top
X32  60.96,93.98 0 top
X33  67.94,93.98 0 top
X34  78.11,93.98 0 top
X35  104.01,93.85 0 top

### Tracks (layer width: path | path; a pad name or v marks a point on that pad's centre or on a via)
0-BUZ
  Top 0.305: D29.A R68.1 | 67.94,84.45 D29.A | 67.94,84.45 69.63,84.45 R69.1 | D29.A 67.31,83.82 | U1.6 38.73,74.3 38.73,73.66 39.37,73.03 54.61,73.03 55.88,74.3 55.88,75.56 57.15,76.83 59.05,76.83 59.69,77.47 60.96,77.47 62.87,79.38 65.41,79.38 66.04,80.01 66.04,81.92 66.67,82.55 67.31,82.55 67.94,83.19 67.94,84.45
0-D0
  Top 0.305: R60.1 D25.A 47.62,84.45 | 47.62,84.45 49.31,84.45 R65.1 | U1.2 48.26,83.81 47.62,84.45
0-D1  (via drill 0.36)
  Top 0.305: R62.1 D26.A 54.39,84.45 R66.1 | 55.24,85.09 55.88,84.45 55.88,80.64 v55.24,80.01
  Top 0.406: 55.24,85.09 55.03,85.09 R66.1
  Bottom 0.305: U1.3 45.72,74.3 46.99,73.03 54.61,73.03 54.61,73.66 55.88,74.93 55.88,75.56 55.24,76.2 v55.24,80.01
0-GRN  (via drill 0.36)
  Top 0.305: D28.A R64.1 | D28.A 64.55,84.45 R61.1 | D28.A 61.59,84.45 | D28.A 62.23,82.87 60.96,81.6 60.96,80.64 60.33,80.01 59.69,80.01 59.05,79.38 59.05,78.11 58.42,77.47 56.83,77.47 56.2,76.83 50.8,76.83 v49.53,78.11
  Bottom 0.305: U1.5 44.45,78.74 48.9,78.74 v49.53,78.11
0-RED  (via drill 0.36)
  Top 0.305: R63.1 D27.A 59.05,84.45 | 59.05,84.45 59.47,84.45 R67.1 | 59.05,84.45 58.42,83.81 58.42,79.38 57.15,78.11 v52.7,78.11
  Bottom 0.305: U1.4 43.18,75.56 44.45,76.83 50.16,76.83 51.44,78.11 v52.7,78.11
1-BUZ
  Top 0.305: R32.1 D24.A 35.78,84.45 36.3,83.93 | 36.3,83.93 R59.1 | 36.3,83.93 35.56,83.19 35.56,78.74 36.2,78.11 36.2,75.56 U1.7
1-D0
  Top 0.305: D20.A R51.1 | R56.1 15.66,83.4 15.24,83.82 14.6,83.82 D20.A | U1.19 71.12,65.41 69.22,63.5 12.06,63.5 10.79,64.77 10.79,77.47 12.06,78.74 12.06,82.55 D20.A | D20.A 12.7,83.18
1-D1
  Top 0.305: R53.1 D21.A 20.54,84.45 R57.1 20.54,83.4 20.32,83.19 20.32,79.38 18.41,77.47 12.7,77.47 11.43,76.2 11.43,65.41 12.7,64.14 68.58,64.14 70.48,66.04 70.48,73.03 U1.18
1-GRN
  Top 0.305: R55.1 D23.A 29.84,84.45 | 29.84,84.45 30.7,84.45 R52.1 | U1.8 31.11,74.93 31.11,76.83 30.48,77.47 30.48,83.81 29.84,84.45
1-RED  (via drill 0.36)
  Top 0.305: R54.1 D22.A 25.62,84.45 R58.1 25.4,82.77 25.4,80.33 v26.99,78.74 | U1.17 66.04,74.3 64.14,71.75 34.92,71.75 33.66,73.66 33.66,77.47 33.34,77.47 v32.7,78.11
  Bottom 0.305: v32.7,78.11 27.62,78.11 v26.99,78.74
5V  (via drill 0.36)  (1 unrouted)
  Top 0.305: U$7.8 64.14,52.7 | 63.5,53.34 62.6,53.34 C4.2 | 81.92,83.19 81.28,82.55 81.28,81.65 C5.2 | R22.2 31.96,19.9 | 69,82.97 R69.2 | 64.14,83.19 64.35,82.97 | v64.14,81.28 63.5,81.92 | R52.2 31.75,80.64 v34.92,77.47 | R42.2 91.22,19.68 | 38.95,19.9 R24.2 39.37,20.32 | R58.2 26.67,80.96 28.26,79.38 28.26,77.79 v29.21,76.83 | C8.2 70.8,48.24 U3.8 66.99,48.58 66.04,49.53 64.14,49.53
  Top 0.406: R76.2 29.21,30.48 27.94,29.21 27.94,27.3 | 64.14,49.53 U$7.8 | R15.2 96.1,90.39 95.25,89.53 93.34,89.53 92.08,88.27 92.08,81.28 86.36,75.56 | U1.5V@2 86.36,75.56 | U1.5V@1 85.72,74.93 86.36,75.56 | v124.46,19.05 123.61,19.9 | R20.2 17.57,19.9 v18.41,19.05 | R21.2 23.91,19.9 v24.77,19.05 | 31.96,19.9 32.17,19.9 | R24.2 39.37,19.68 | R29.2 45.72,20.95 v46.99,22.23 | R30.2 53.34,21.59 52.07,22.86 v50.16,22.86 | R31.2 60.96,20.95 61.59,21.59 v62.87,21.59 | v68.58,21.59 R25.2 | R40.2 78.95,19.9 v79.38,20.32 | R36.2 100.33,21.59 v99.69,22.23 | R48.2 106.68,20.32 v107.95,21.59 | v116.2,21.59 114.52,19.9 | v16.51,78.74 R56.2 | R57.2 21.59,79.38 v22.23,78.74 | 69,82.97 68.58,82.55 68.58,81.92 v69.22,81.28 | 64.35,82.97 R61.2 | 64.14,83.19 63.5,82.55 63.5,81.92 | R66.2 53.76,82.97 53.34,82.55 53.34,81.92 | R59.2 v36.83,79.38 | v53.98,81.28 53.34,81.92 | R65.2 52.28,82.97 53.34,81.92 | v59.69,81.28 R67.2 | 63.5,53.34 64.14,52.7 64.14,57.15 64.77,57.78 65.83,57.78 R34.1 66.25,58 67.31,59.05 68.36,59.05 R33.1 | R41.2 85.51,19.27 86.36,18.41 v86.36,17.78 | 80.64,80.01 v80.01,80.64 | v33.66,19.05 32.38,20.32 32.17,20.32 R22.2 | R42.2 93.13,19.9 93.34,19.68 v93.34,17.78 | 39.37,20.32 40.01,20.32 v41.27,19.05
  Top 0.61: 123.61,19.9 R50.2 | 81.28,82.55 81.92,81.92 81.92,80.01 80.64,80.01 | R59.2 41.49,81.7 v43.18,80.01 | U1.5V@0 27.94,27.3
  Top 0.813: C2.+ 101.76,39.13 R2.1 101.76,34.42 L1.1 97.47,32.7 v95.89,31.11 | 64.14,49.53 57.78,43.18 43.81,43.18 27.94,27.3 | U1.5V@1 83.82,76.2 81.92,78.11 81.92,80.01 81.92,81.02 C5.2 | IC1.8 81.92,83.19 81.92,81.92 81.92,81.28
  Bottom 0.305: v79.38,20.32 80.01,19.68 80.01,19.05 | v107.95,21.59 108.58,20.95 108.58,19.05 | v116.2,21.59 116.84,20.95 116.84,19.05 | 99.69,19.05 v99.69,22.23
  Bottom 0.406: v46.99,22.23 46.99,20.95 47.62,20.32 47.62,19.05 | v50.16,22.86 49.53,22.86 48.9,22.23 48.9,19.05 | v62.87,21.59 63.5,20.95 63.5,19.05 | v68.58,21.59 69.22,22.23 71.12,20.32 71.12,19.05 | v16.51,78.74 v22.23,78.74 24.77,78.74 26.67,76.83 v29.21,76.83 34.29,76.83 v34.92,77.47 v36.83,79.38 | 93.34,19.05 v93.34,17.78 | 86.36,19.05 v86.36,17.78
  Bottom 0.61: v43.18,80.01 48.9,80.01 49.53,80.64 52.7,80.64 v53.98,81.28 55.24,82.55 57.78,82.55 59.05,81.28 v59.69,81.28 v64.14,81.28 v69.22,81.28 71.75,81.28 72.39,81.92 74.3,81.92 75.56,80.64 v80.01,80.64
  Bottom 0.813: U1.5V@2 90.81,74.93 93.34,72.39 93.34,33.66 v95.89,31.11 99.69,27.3 99.69,19.05 | 35.56,19.05 v41.27,19.05 47.62,19.05 48.9,19.05 63.5,19.05 71.12,19.05 80.01,19.05 86.36,19.05 93.34,19.05 99.69,19.05 | 99.69,19.05 108.58,19.05 116.84,19.05 v124.46,19.05 | 35.56,19.05 U1.5V@0 | v18.41,19.05 v24.77,19.05 v33.66,19.05 35.56,19.05
GND  (via drill 0.36)
  Bottom 0.406: v69.85,13.97 v78.11,13.97
  other vias: 8.26,80.01 13.97,78.74 40.64,84.45 24.77,13.97 33.02,13.97 40.01,13.97 46.99,13.97 54.61,13.97 62.23,13.97 40.01,79.38 73.03,20.95 44.45,22.86 95.89,22.23 86.36,20.32 74.3,84.14 53.66,79.38 60.96,79.06 35.56,53.34 14.61,53.34 123.19,53.34 102.23,64.14 85.72,13.97 93.98,13.97 100.97,13.97 108.58,13.97 116.2,13.97 123.19,89.53 123.19,23.5 123.19,13.97 143.51,85.09 143.51,54.61 142.88,13.97 97.16,39.37
  pour Top (rank 2): 1.27,100.33 182.88,100.33 182.88,1.27 1.27,1.27
  pour Bottom (rank 2): 1.27,100.33 182.88,100.33 182.88,1.27 1.27,1.27
  pour Bottom (isolate 1.27): 147.32,97.79 168.91,97.79 168.91,3.81 147.32,3.81
INPUT0
  Top 0.305: R16.1 D4.A 15.46,17.15 R20.1 15.46,18.2 15.24,18.41 15.24,22.86 16.51,24.13 39.37,24.13 40.64,25.4 U1.A0
INPUT1
  Top 0.305: R17.1 D5.A 21.81,17.15 R21.1 24.55,16.51 26.04,16.51 26.67,17.14 26.67,22.23 27.94,23.5 40.01,23.5 U1.A1
INPUT2
  Top 0.305: R18.1 D6.A 30.7,17.15 R22.1 | U1.A2 43.18,24.13 41.91,24.13 40.64,22.86 36.2,22.86 34.92,21.59 34.92,17.14 34.29,16.51 32.38,16.51 31.75,17.14 R22.1 | R22.1 31.96,18.41
INPUT3
  Top 0.305: R19.1 D7.A 38.32,17.15 38.84,17.67 | 38.84,17.67 R24.1 | U1.A3 45.72,24.13 45.72,22.23 44.45,20.95 44.45,19.68 43.5,18.73 42.55,18.73 41.27,17.46 41.27,17.14 40.64,16.51 40.01,16.51 38.84,17.67
INPUT4
  Top 0.305: R23.1 D8.A 44.67,17.15 R29.1 47.41,18.2 48.26,19.05 48.26,24.13 U1.A4
INPUT5
  Top 0.305: R26.1 D9.A 52.29,17.15 R30.1 55.03,18.2 55.88,19.05 55.88,20.32 54.61,21.59 54.61,22.86 53.34,24.13 U1.A5
INPUT6
  Top 0.305: R27.1 D10.A | D10.A 59.91,17.15 R31.1 | U1.A6 55.88,21.59 57.15,20.32 57.15,18.42 D10.A
INPUT7
  Top 0.305: R28.1 D11.A | D11.A 67.53,17.15 R25.1 | D11.A 65.4,17.15 64.77,17.78 64.77,22.86 63.5,24.13 60.96,24.13 U1.A7
INPUT8
  Top 0.305: R35.1 D12.A | D12.A 76.42,17.15 R40.1 | D12.A 74.29,17.15 71.75,19.05 71.75,20.95 69.85,22.86 67.31,22.86 U1.A8
INPUT9
  Top 0.305: R37.1 D13.A 81.91,17.15 81.28,17.78 81.28,20.95 80.64,21.59 79.38,21.59 78.74,22.23 71.75,22.23 69.85,24.13 67.31,24.13 66.04,25.4 U1.A9 | R41.1 84.04,17.15
  Top 0.406: D13.A 84.45,17.15 R41.1
INPUT10
  Top 0.305: 88.9,16.51 R38.1 | 88.9,16.51 D14.A 90.39,17.15 R42.1 | 88.9,16.51 87.63,17.78 87.63,21.59 84.45,21.59 83.19,22.23 80.01,22.23 79.38,22.86 72.39,22.86 U1.A10
INPUT11
  Top 0.305: D15.A R39.1 | D15.A 99.28,17.15 R36.1 | U1.A11 71.12,25.4 73.03,23.5 79.69,23.5 80.33,22.86 83.82,22.86 85.09,22.23 90.17,22.23 90.81,21.59 94.61,21.59 95.25,20.95 95.25,17.14 D15.A
INPUT12
  Top 0.305: D16.A R43.1 | D16.A 105.63,17.15 R48.1 | U1.A12 73.66,24.77 74.3,24.13 80.01,24.13 80.64,23.5 84.45,23.5 85.72,22.86 91.44,22.86 92.08,23.5 100.25,23.5 100.56,23.19 | 100.56,23.19 102.23,20.95 102.23,17.78 102.87,17.14 D16.A | 100.56,23.19 100.33,23.5
INPUT13
  Top 0.305: D17.A R45.1 | D17.A 113.25,17.15 R49.1 | D17.A 111.12,17.15 109.86,18.41 109.86,22.86 108.58,24.13 91.44,24.13 90.81,23.5 86.36,23.5 85.09,24.13 80.96,24.13 80.33,24.77 76.83,24.77 76.2,25.4 U1.A13
INPUT14
  Top 0.305: D18.A R46.1 | D18.A 120.87,17.15 R50.1 | D18.A 118.74,17.15 118.11,17.78 118.11,24.13 117.47,24.77 90.81,24.77 90.17,24.13 87,24.13 85.72,24.77 81.28,24.77 80.64,25.4 80.01,25.4 U1.A14
INPUT15-BAT
  Top 0.305: R72.1 R73.1 131.66,18.63 132.08,19.05 132.08,19.69 | 132.08,19.69 D19.A | 132.08,19.69 132.08,21.59 127,26.67 90.17,26.67 87.63,29.21 83.82,29.21 U1.A15
ISOLATED  (via drill 0.36)
  other vias: 149.86,93.34 164.47,95.25 154.94,5.71 148.59,46.99
  pour Top (isolate 1.422): 147.32,97.79 168.91,97.79 168.91,3.81 147.32,3.81
  pour Bottom (isolate 1.422): 147.32,97.79 168.91,97.79 168.91,3.81 147.32,3.81 147.32,4.45
N$1
  Top 0.813: R3.1 99.91,36.63 R2.2
N$2
  Top 0.813: R4.1 94.84,37.53 R3.2
N$3  (via drill 0.6)  (1 unrouted)
  Top 0.61: U$1.7 U$1.8 | U$1.1 110.92,44.02 v112.39,42.55 | 112.39,37.47 112.39,37.19 R5.1 | 112.39,37.47 112.39,38.46 | 110.95,37.95 111.91,37.95 112.39,37.47
  Top 0.813: U$1.8 110.95,37.95
  Bottom 0.61: v112.39,38.73 v112.39,42.55
N$4
  Top 1.778: X35.2 106.51,86.32 F1.1A
N$5
  Top 0.61: R1.1 94.84,44.34 R4.2
  Top 0.813: U$1.5 107.06,38.99 102.87,43.18 97.79,43.18 96.52,44.45 94.83,44.45 R1.1
N$6
  Top 0.61: U$1.3 108.33,45.66 107.95,46.04 107.95,46.27 C3.1
N$8
  Top 0.813: F1.2A 105.41,68.58 | D2.A 92.71,68.58
  Top 1.778: R6.1 110.05,74.36 105.16,69.47 105.16,67.94 | 105.16,67.94 F1.2A | 105.16,67.94 93.45,67.94 D2.A
N$9
  Top 0.305: LED2.C R8.2
N$10
  Bottom 2.54: K1.2 151.76,71.12 155.57,74.93 162.56,74.93 163.19,75.56 165.63,75.56 X2.2
N$11
  Bottom 2.54: X2.3 165.09,72.38 164.47,71.75 159.38,71.75 K1.3
N$12
  Bottom 2.54: X2.1 161.93,79.38 160.66,78.11 156.84,78.11 K1.4
N$13
  Bottom 2.54: X3.2 163.19,65.41 162.56,64.77 154.94,64.77 K2.2
N$14
  Bottom 2.54: K2.3 159.38,61.59 165.64,61.59 X3.3
N$15
  Bottom 2.54: K2.4 156.84,67.94 160.66,67.94 161.29,68.58 165.63,68.58 X3.1
N$16
  Bottom 2.54: X4.2 161.61,54.93 160.66,53.98 154.31,53.98 K3.2
N$17
  Bottom 2.54: K3.3 162.56,50.8 163.19,51.44 X4.3
N$18
  Bottom 2.54: X4.1 160.66,58.43 160.02,57.78 156.84,57.78 K3.4
N$19
  Bottom 2.54: X5.2 154.94,44.45 K4.2
N$20
  Bottom 2.54: K4.3 165.64,40.64 X5.3
N$21
  Bottom 2.54: X5.1 164.16,47.95 163.83,47.62 156.84,47.62 K4.4
N$22
  Bottom 2.54: X6.2 154.62,33.97 K5.2
N$23
  Bottom 2.54: K5.3 X6.3
N$24
  Bottom 2.54: K5.4 156.84,37.47 X6.1
N$25
  Bottom 2.54: X7.2 154.31,23.5 K6.2
N$26
  Bottom 2.54: K6.3 165.63,20.32 X7.3
N$27
  Bottom 2.54: X7.1 157.16,27 K6.4
N$28
  Bottom 2.54: X8.2 162.88,13.02 161.93,13.97 154.94,13.97 K7.2
N$29
  Bottom 2.54: K7.3 161.29,10.16 161.93,9.53 X8.3
N$30
  Bottom 2.54: K7.4 156.84,17.14 163.19,17.14 163.83,16.51 X8.1
N$31
  Bottom 2.54: X9.2 158.75,86.36 156.21,83.82 153.67,83.82 K8.2
N$32
  Bottom 2.54: K8.3 160.02,82.55 165.64,82.55 X9.3
N$34
  Top 0.305: LED3.C R9.2
N$35
  Top 0.305: LED1.C R7.2
N$36
  Top 0.305: LED4.C R10.2
N$37
  Top 0.305: LED5.C R11.2
N$38
  Top 0.305: LED6.C R12.2
N$39
  Top 0.305: LED7.C R13.2
N$40
  Top 0.305: LED8.C R14.2
N$41
  Top 0.406: LED9.A 92.71,93.13 R15.1
N$46
  Top 0.61: X30.2 48.16,93.88 44.45,90.17 F2.2
N$47
  Top 0.61: F3.2 11.43,90.17 12.06,90.81 13.34,90.81 14.61,92.08 16.51,92.08 17.14,92.71 17.14,93.4 X26.2
N$49
  Top 0.305: IC1.6 81.28,85.72 80.64,86.36 80.64,87 80.01,87.63 JP1.2 78.11,88.39 82.8,93.09 82.8,96.39 81.92,97.28 77.34,97.28 76.58,96.52 76.58,94.11 X34.1
N$50
  Top 0.305: R16.2 13.49,12.64 13.49,8.36 X10.2
N$51
  Top 0.305: R17.2 20.32,8.51 X11.2
N$52
  Top 0.305: R18.2 28.73,12.64 28.73,8.36 X12.2
N$53
  Top 0.305: R19.2 36.35,12.64 36.35,8.99 X13.2
N$54
  Top 0.305: R23.2 43.18,8.84 X14.2
N$55
  Top 0.305: R26.2 50.8,9.47 X15.2
N$56
  Top 0.305: R27.2 58.42,10.11 X16.2
N$57
  Top 0.305: R28.2 66.04,10.74 X17.2
N$58
  Top 0.305: U$7.1 64.14,45.59 Q1.1
N$59
  Top 0.305: U$7.2 65.41,43.81 Q1.4
N$60
  Top 0.406: BAT1.1 66.04,35.88 67.63,37.47 67.63,44.77 66.67,45.72 U$7.3
N$61
  Top 0.305: R35.2 74.08,13.12 70.48,9.53 70.48,8.2 X18.2
N$62
  Top 0.305: R37.2 81.7,13.12 77.47,8.89 77.47,8.2 X19.2
N$63
  Top 0.305: R38.2 88.05,13.12 84.45,9.53 84.45,8.2 X20.2
N$64
  Top 0.305: R39.2 96.94,13.12 93.98,10.16 92.71,10.16 91.44,8.89 91.44,8.2 X21.2
N$65
  Top 0.305: R43.2 103.92,13.12 102.87,12.06 100.33,12.06 97.79,9.53 97.79,7.88 X22.2
N$66
  Top 0.305: R45.2 110.28,13.12 107.95,10.79 106.68,10.79 104.78,8.89 104.78,7.88 X23.2
N$67
  Top 0.305: R46.2 117.89,13.12 114.94,10.16 113.03,10.16 111.12,8.26 111.38,8.26 X24.2
N$68
  Top 0.305: R47.2 124.88,13.12 122.56,10.79 120.65,10.79 118.75,8.89 118.75,7.88 X25.2
N$69
  Top 0.305: R51.2 13.97,90.17 14.61,90.81 19.68,90.81 20.32,91.44 20.32,93.09 X27.1
N$70
  Top 0.305: R53.2 19.05,88.9 19.68,89.53 22.86,89.53 24.77,91.44 24.77,93.72 X27.2
N$71
  Top 0.305: R54.2 24.13,88.9 25.4,90.17 26.67,90.17 27.94,91.44 27.94,93.72 X28.1
N$72
  Top 0.305: X28.2 31.59,90.65 31.11,90.17 30.48,90.17 29.21,88.9 R55.2
N$73
  Top 0.305: X29.1 35.08,89.69 34.29,88.9 R32.2
N$74
  Top 0.305: X31.2 55.78,93.88 52.07,90.17 R62.2
N$75
  Top 0.305: X31.1 52.39,93.88 R60.2
N$76
  Top 0.305: R63.2 57.15,91.82 X32.1
N$77
  Top 0.305: R64.2 62.23,93.4 X32.2
N$78
  Top 0.305: R68.2 67.31,92.77 X33.1
N$79
  Top 0.305: R76.1 JP2.2
N$81  (via drill 0.6)
  Top 0.61: D1.C 109.6,46.42 U$1.2 109.6,46.29 v109.54,46.35 | v109.54,34.92 109.54,33.05 L1.2
  Bottom 0.61: v109.54,34.92 v109.54,46.35
N$82
  Top 0.305: R47.1 R71.2
N$83
  Top 0.305: R72.2 128.27,15.66 128.27,18.41 127.64,19.05 127.22,19.05 R71.1
N$84
  Top 0.305: X29.2 38.58,89.27 R74.2
N$85
  Top 0.305: R75.2 72.39,89.53 69.85,92.08 69.85,93.72 X33.2
N$86
  Top 0.305: JP1.1 78.74,83.82 78.11,83.19 78.11,82.77 R70.2
N$115  (via drill 0.36)
  other vias: 78.11,60.96
N$116  (via drill 0.36)
  other vias: 64.14,60.96
N$118  (via drill 0.36)
  other vias: 69.22,38.73
N$255
  Bottom 2.54: K8.4 157.48,90.17 165.64,90.17 X9.1
OUTPUT0
  Top 0.254: 88.27,61.59 87.63,62.23 U1.31
  Top 0.305: 88.27,61.59 ULN1.1
OUTPUT0-R
  Top 0.305: 140.55,88.48 K8.5
  Top 0.406: 140.55,88.48 R14.1 134.2,88.48 133.35,87.63 133.35,79.38 130.18,76.2 120.65,76.2 106.05,61.59 ULN1.18
OUTPUT1
  Top 0.254: 88.27,60.33 87.63,60.96 85.09,60.96 U1.32
  Top 0.305: 88.27,60.33 ULN1.2
OUTPUT1-R
  Top 0.305: 140.55,78.32 K1.5
  Top 0.406: 140.55,78.32 R7.1 135.47,78.32 132.08,74.93 120.65,74.93 106.05,60.33 ULN1.17
OUTPUT2
  Top 0.254: 88.27,59.05 87.63,59.69 U1.33
  Top 0.305: 88.27,59.05 ULN1.3
OUTPUT2-R
  Top 0.305: R8.1 136.94,67.94
  Top 0.406: K2.5 140.55,68.16 R8.1 136.74,68.58 135.25,68.58 132.72,71.12 118.11,71.12 106.05,59.05 ULN1.16
OUTPUT3
  Top 0.254: 88.27,57.78 87.63,58.42 85.09,58.42 U1.34
  Top 0.305: 88.27,57.78 ULN1.4
OUTPUT3-R
  Top 0.406: R9.1 140.55,58 K3.5 | R9.1 137.16,58.42 | ULN1.15 106.05,57.78 118.11,69.85 131.44,69.85 134.62,66.67 134.62,62.23 135.89,60.96 135.89,59.05 136.53,58.42 136.74,58.42 R9.1
OUTPUT4
  Top 0.254: 88.27,56.52 87.63,57.15 U1.35
  Top 0.305: 88.27,56.52 ULN1.5
OUTPUT4-R
  Top 0.305: R10.1 137.58,48.26
  Top 0.406: 137.58,48.26 K4.5 | ULN1.14 106.05,56.52 118.11,68.58 130.18,68.58 133.35,65.41 133.35,61.59 134.62,60.33 134.62,51.02 137.16,48.48 R10.1
OUTPUT5
  Top 0.254: 88.27,55.24 87.63,55.88 85.09,55.88 U1.36
  Top 0.305: 88.27,55.24 ULN1.6
OUTPUT5-R
  Top 0.305: R11.1 137.16,38.1
  Top 0.406: 137.16,38.1 K5.5 | ULN1.13 106.05,55.24 118.11,67.31 128.91,67.31 132.08,64.14 132.08,60.33 133.35,59.05 133.35,50.16 134.62,48.9 134.62,39.59 136.53,37.68 R11.1
OUTPUT6
  Top 0.305: ULN1.7 87,53.98 U1.37
OUTPUT6-R
  Top 0.406: K6.5 140.55,27.52 R12.1 135.25,27.52 134.62,28.16 134.62,37.47 133.35,38.73 133.35,48.9 132.08,50.16 132.08,59.05 130.81,60.33 130.81,62.87 127.64,66.04 118.11,66.04 106.05,53.98 ULN1.12
OUTPUT7
  Top 0.254: 89.53,52.7 87.63,50.8 85.09,50.8 U1.38
  Top 0.305: 89.53,52.7 ULN1.8
OUTPUT7-R
  Top 0.406: K7.5 140.55,17.36 R13.1 136.94,17.14 135.25,17.14 134.62,17.78 134.62,26.04 133.35,27.3 133.35,37.47 132.08,38.73 132.08,48.9 130.81,50.16 130.81,59.05 129.54,60.33 129.54,61.59 126.36,64.77 118.11,64.77 106.05,52.7 ULN1.11
RESET
  Top 0.305: S1.1 S1.2 24.77,38.1 JP2.1 26.67,33.02 22.86,29.21 U1.RESET
RS485-B
  Top 0.305: 81.28,84.45 IC1.7 | 81.28,84.45 80.01,83.19 80.01,82.97 R70.1 | 81.28,84.45 80.01,85.72 80.01,86.36 76.2,86.36 75.56,87 75.56,89.59 X34.2
RS485-D  (via drill 0.36)
  Top 0.305: IC1.4 86.36,87 85.72,86.36 85.72,82.55 85.09,81.92 v85.09,80.64 | U1.14 60.33,76.83 61.59,76.83 63.5,78.74 67.31,78.74 67.94,79.38 73.03,79.38 73.66,80.01 v74.3,80.01
  Bottom 0.305: v85.09,80.64 83.82,79.38 74.93,79.38 v74.3,80.01
RS485-ENA  (via drill 0.36)
  Top 0.305: v89.85,84.45 88.27,84.45 | 88.27,84.45 IC1.2 | IC1.3 87.69,85.03 88.27,84.45
  Bottom 0.305: U1.16 63.5,76.2 64.77,77.47 67.94,77.47 68.58,78.11 85.72,78.11 89.85,81.92 v89.85,84.45
RS485-R  (via drill 0.36)
  Top 0.305: IC1.1 87.63,83.19 87.63,81.92 v87,81.28
  Bottom 0.305: U1.15 64.14,78.11 67.31,78.11 67.94,78.74 85.09,78.74 87,80.64 v87,81.28
SCL
  Top 0.305: R34.2 66.04,55.88 66.67,55.24 U$7.6 66.67,50.16 67.31,49.53 68.58,49.53 68.58,49.85 69.85,51.12 U3.6 | U1.21 76.2,73.66 74.93,72.39 74.93,52.39 73.66,51.12 U3.6 | U3.6 71.44,51.12
SDA
  Top 0.305: U$7.5 67.94,52.7 67.94,55.24 68.58,55.88 R33.2 69,57.15 69.85,57.15 73.66,60.96 U1.20
  Top 0.406: U3.5 68.26,52.39 67.94,52.7
VCC  (via drill 0.36)
  Top 0.61: LED8.A 140.75,81.5 K8.1 | LED1.A 140.75,71.34 K1.1 | LED2.A 140.75,61.18 K2.1 | LED3.A 140.75,51.02 K3.1 | LED4.A 140.75,40.86 K4.1 | 141.6,30.48 K5.1 137.38,30.48 LED5.A | 141.6,20.32 K6.1 137.38,20.32 LED6.A | F2.1 44.32,86.23 43.81,85.72 v43.81,84.45 | 140.75,10.38 K7.1 137.38,10.16 LED7.A
  Top 0.813: D2.C 93.98,76.09 93.98,76.83 | 93.98,76.83 v93.98,80.64 D3.C | F3.1 11.43,85.09 v9.53,83.19 | 93.98,76.83 92.71,75.56 91.44,75.56 88.9,73.03 88.9,66.04 90.81,64.14 95.89,64.14 96.52,63.5 96.52,53.34 98.42,51.44 ULN1.10 107,51.44 108.9,49.53 112.39,49.53 114.3,47.62 114.3,45.33 C1.+ 114.38,45.4 114.94,45.4 114.6,45.07 114.6,40.96 | v123.19,35.56 116.99,35.56 R5.2 114.6,40.96 | U$1.6 108.33,40.07 108.9,40.64 114.29,40.64 114.6,40.96
  Bottom 0.406: K6.1 139.7,20.32 137.16,17.78
  Bottom 0.61: v93.98,80.64 93.98,83.82 92.71,85.09 92.71,85.72 89.53,88.9 81.28,88.9 80.01,90.17 45.72,90.17 | v43.81,84.45 43.81,88.27 45.72,90.17 | 45.72,90.17 16.51,90.17 v9.53,83.19 | 137.16,17.78 137.16,12.7 139.48,10.38 140.75,10.38 K7.1 | 139.7,30.48 K5.1 | 139.7,30.48 137.16,29.21 137.16,24.13 K6.1 | K8.1 139.06,81.28 137.79,80.01 137.79,72.39 139.06,71.12 | 139.06,71.12 K1.1 | 139.06,71.12 137.79,69.85 137.79,62.45 139.06,61.18 140.75,61.18 K2.1 139.06,60.96 137.79,59.69 137.79,52.29 139.06,51.02 140.75,51.02 K3.1 139.06,50.8 137.79,49.53 137.79,42.13 139.06,40.86 | 139.06,40.86 140.75,40.86 K4.1 | 139.7,30.48 139.7,34.29 138.43,35.56 137.79,36.2 137.79,39.59 139.06,40.86
  Bottom 0.813: v123.19,35.56 138.43,35.56

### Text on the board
_tsilk: 12-15VDC IN | A | B | GND | +12V | D0 | D1 | LED | LED | BUZ | DRN | GND | +12V | D0 | D1 | LED | LED | BUZ | DRN | - | + | POWER | PWR | READER1 | READER2 | RS485 | NC | 0 | COM | 0 | 2A FUSE | NO | NC | 1 | COM | 1 | NO | NC | 2 | 2 | COM | NO | 3 | NC | 3 | COM | NO | 4 | NC | 4 | COM | RESET | NO | rev 1a8 | 5 | NC | Open Access Mega 3 | COM | 5 | NO | 6 | NC | COM | 6 | NO | 7 | NC | COM | 7 | ALARMS | NO | S0 | GND | S1 | GND | S0 | S2 | GND | S3 | GND | S4 | GND | S5 | GND | S6 | GND | S7 | GND | S8 | GND | S9 | GND | S10 | GND | S11 | GND | S12 | GND | S13 | GND | S14 | GND | SV | GND
_bsilk: Open Access Mega is licensed under a Creative Commons | Attribution-ShareAlike 3.0 Unported License. | Based on a work at www.accxproducts.com. | (c) 2011 ACCX Producs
